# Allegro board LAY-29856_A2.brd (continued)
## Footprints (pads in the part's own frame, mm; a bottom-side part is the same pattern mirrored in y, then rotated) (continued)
WLCSP12_0P4_1P38X1P68MM_SMDP
  round 0.254 smd: A1(-0.4,0.6) A2(0,0.6) A3(0.4,0.6) B1(-0.4,0.2) B2(0,0.2) B3(0.4,0.2) C1(-0.4,-0.2) C2(0,-0.2) C3(0.4,-0.2) D1(-0.4,-0.6) D2(0,-0.6) D3(0.4,-0.6)
XQFN8_1P45X1P25MM
  rect 0.787x0.203 smd: 1(-0.75,0)
  rect 0.203x0.711 smd: 2(-0.4,-0.65) 3(0,-0.65) 4(0.4,-0.65) 6(0.4,0.65) 7(0,0.65) 8(-0.4,0.65)
  rect 0.711x0.203 smd: 5(0.75,0)
XTAL2-3P2X1P5-SM
  rect 1.092x1.905 smd: 1(-1.25,0) 2(1.25,0)
XTAL3_3P35X1P45_SM
  rect 0.406x2.108 smd: 1(1.2,0) 2(0,0) 3(-1.2,0)
XTL4_2P1X1P7MM_SM
  rect 0.762x0.711 smd: 1(-0.675,-0.5) 2(0.675,-0.5) 3(0.675,0.5) 4(-0.675,0.5)

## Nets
5V_SDA_PSW: C166.1 R210.1 U25.C2(VBUS1) U25.D1(VBUS2) U25.D2(VBUS3)
5V_SYS: C40.1 C41.1 C62.1 C63.1 C179.1 C180.1 D14.A J20.8 L20.2 R7.1 R38.1 R62.1 R71.1 R82.1 U3.1(IN) U3.3(S\H\D\N\) U6.1(IN)
5V_USB_OTG: C78.1 C81.1 C84.1 L3.2 R312.1 U1.59(USB_OTG1_VBUS) U7.C2(VBUS1) U7.D1(VBUS2) U7.D2(VBUS3)
5V_USB_OTG_S: J1.3(A2) R312.2
GND: C1.2 C2.2 C3.2 C4.2 C6.2 C7.2 C8.2 C9.2 C10.2 C11.2 C12.2 C13.2 C14.2 C15.2 C16.2 C17.2 C18.2 C19.2 C20.2 C21.2 C22.2 C23.2 C24.2 C25.2 C26.2 C28.2 C29.2 C30.2 C31.2 C32.2 C33.2 C35.2 C36.2 C37.2 C38.2 C39.2 C40.2 C41.2 C42.2 C43.2 C44.2 C45.2 C46.2 C47.2 C48.2 C49.2 C50.2 C51.2 C52.2 C53.2 C54.2 C55.2 C56.2 C57.2 C58.2 C59.2 C60.2 C62.2 C63.2 C64.2 C65.2 C66.2 C67.2 C68.2 C69.2 C70.2 C71.2 C72.2 C73.2 C74.2 C75.2 C76.2 C77.2 C78.2 C79.2 C80.2 C81.2 C82.2 C83.2 C84.2 C85.2 C86.2 C87.2 C88.1 C89.2 C90.2 C91.2 C92.2 C93.2 C94.2 C95.2 C96.2 C97.2 C98.2 C99.2 C100.2 C101.1 C104.2 C105.2 C106.2 C107.1 C108.2 C109.2 C110.1 C116.2 C117.2 C118.2 C119.2 C120.1 C121.1 C124.2 C125.2 C126.2 C127.2 C128.2 C129.2 C130.2 C131.2 C132.2 C133.2 C134.2 C135.2 C136.2 C137.2 C138.2 C139.2 C140.2 C141.2 C142.2 C143.2 C144.2 C145.2 C146.2 C147.2 C148.2 C149.2 C150.2 C151.2 C152.2 C153.2 C154.2 C155.2 C156.2 C157.2 C158.2 C159.2 C160.2 C161.2 C162.2 C163.2 C164.2 C165.2 C166.2 C167.2 C168.2 C169.2 C170.2 C171.2 C172.2 C173.2 C174.2 C175.2 C176.2 C177.2 C178.2 C179.2 C180.2 D1.A(ANODE) D3.4(CATHODE2) D11.3(ANODES) H1.1(NC_1) H2.1(NC_1) H3.1(NC_1) H4.1(NC_1) J1.7(A4) J1.8(B4) J1.9(A5) J1.10(B5) J2.2 J2.3 J7.1 J9.5(P5) J10.2 J11.1 J14.10(CHS_GND) J15.6(VSS) J15.SH1(GND1) J15.SH2(GND2) J15.SH3(GND3) J15.SH4(GND4) J16.4 J16.6 J16.8 J16.10 J16.12 J16.14 J16.16 J16.18 J16.20 J19.7 J20.6 J20.7 J23.5(P5) J29.3(A2) J29.5(A3) L5.2 L10.1 L12.2 Q1.3(G) Q4.2(SOURCE) Q9.1(SOURCE) R11.2 R31.2 R34.2 R42.2 R53.2 R54.2 R55.2 R57.2 R67.2 R70.2 R75.2 R86.1 R91.2 R103.1 R117.2 R120.2 R121.2 R122.2 R125.2 R126.2 R127.2 R131.2 R133.2 R134.2 R135.2 R137.2 R140.2 R141.2 R150.2 R151.2 R152.2 R178.2 R193.2 R196.2 R201.2 R203.2 R205.2 R211.2 R213.2 R244.2 R246.2 R248.2 R253.1 R254.1 R255.1 R256.1 R257.1 R258.1 R259.1 R260.1 R261.1 R262.1 R263.1 R264.1 SW1.3(NO1) SW1.6(NO2) SW2.1(A1) SW2.2(A2) SW3.1(A1) SW3.2(A2) SW4.1(A1) SW4.2(A2) SW5.1(A1) SW5.2(A2) TP2.1 TP3.1 TP4.1 TP5.1 TVS1.1(A1) TVS2.1(A1) TVS3.1(A1) TVS4.1(A1) TVS5.1(A1) U1.6(VSS1) U1.35(DCDC_GND) U1.40(VSS2) U1.51(TEST_MODE) U1.60(VSS3) U1.64(NGND_KEL0) U1.70(VSS4) U1.85(VSS5) U1.103(VSS6) U1.113(VSS7) U1.135(VSS8) U2.1(GND) U3.2(GND) U4.4(PGND) U4.6(AGND) U5.1(GND) U6.2(GND) U7.B3(GND1) U7.C3(GND2) U7.D3(GND3) U8.7(GND) U9.2(GND) U10.9(DGND) U10.20(SPKGND2) U10.24(SPKGND1) U10.28(AGND) U10.33(GND_PADDLE) U11.1(GND) U11.33(PADDLE) U12.2(A2) U13.4(GND) U14.6(VSSQ1) U14.12(VSSQ2) U14.28(VSS1) U14.41(VSS2) U14.46(VSSQ3) U14.52(VSSQ4) U14.54(VSS3) U15.4(GND) U16.2(VSS1) U16.8(VSSA) U16.33(EPAD) U17.2(GND) U18.2(A2) U19.2(A2) U20.2(A2) U21.2(GND) U22.4(GND) U22.5(DIR) U23.2(GND) U24.2(GND) U25.B3(GND1) U25.C3(GND2) U25.D3(GND3) U26.3(RSVD1) U26.5(GND1) U26.12(GND2) U26.13(RSVD2) U27.B2(GND) Y3.2 Y4.2 Y4.4
P3V3_SDA: C153.1 C154.1 C155.1 C156.1 C157.1 C163.1 J29.1(A1) R180.1 R181.1 R182.1 R183.2 R185.1 R194.1 R198.1 R202.1 R206.1 R207.1 R209.1 U15.1(VCCA) U16.1(VDD1) U16.7(VDDA) U16.11(VBAT) U17.5(VCC) U21.1(VCCA) U22.1(VCCA) U23.1(VCCA) U24.1(VCCA)
P5V0_SDA_USB_CONN_VBUS: J23.1(P1) L11.1 U18.1(A1)
P5V_SDA: C159.1 C164.1 C165.1 L11.2 R195.1 R200.1 R208.1 R212.1 U16.6(VREGIN) U25.B1(VINT1) U25.B2(VINT2) U25.C1(VINT3)
P5V_SDA_S: J1.5(A3) R208.2 R210.2
VDD_COIN_3V: D6.A J7.2 R17.1
VDD_HIGH_IN_3V3: C56.1 J5.1 R14.1 R45.2 R49.2
VDD_HIGH_IN_MCU: C19.1 C20.1 J5.2 R14.2 U1.69(VDD_HIGH_IN)
VDD_SNVS_3V3: C48.1 C60.1 D4.A R25.1 R36.2 R37.2 U5.4(VCC)
VDD_SNVS_IN: C23.1 J6.2 R16.2 R26.1 U1.55(VDD_SNVS_IN)
VDD_SOC_IN: C8.1 C9.1 C10.1 C11.1 C12.1 C13.1 C14.1 C15.1 C16.1 C17.1 C18.1 J4.1 R13.1 U1.5(VDD_SOC_IN1) U1.31(VDD_SOC_IN2) U1.39(VDD_SOC_IN3) U1.86(VDD_SOC_IN4) U1.102(VDD_SOC_IN5) U1.114(VDD_SOC_IN6) U1.134(VDD_SOC_IN7)
VDD_USB_3V: C79.1 C80.1 U1.61(VDD_USB_CAP)
VDDA_ADC_3P3_MCU: C6.1 C7.1 J3.2 R12.2 U1.73(VDDA_ADC_3P3)
VDDA_ADC_3V3: C47.1 J3.1 R12.1 R35.2
AUD_INT: R83.1 R84.1 U1.88(GPIO_AD_B1_04)
CAN1_H: C88.2 D11.2(CATHODE2) FL1.1 J10.1 R76.2 R77.1
CAN1_L: C90.1 D11.1(CATHODE1) FL1.2 J10.3 R78.2 R79.2
CAN1_RX: U1.32(GPIO_SD_B1_01) U9.4(RXD)
CAN1_TX: U1.33(GPIO_SD_B1_00) U9.1(TXD)
CAN_STBY: R74.1 R161.2 U1.76(GPIO_AD_B1_13)
CAN_VIO_3V3: C87.1 R72.1 R73.1 U9.5(VIO)
DC_5V_IN: C4.1 J2.1 Q1.1(D1) Q1.2(D2) Q1.5(D5) Q1.6(D6) Q1.7(D7) R1.1 R2.1 R6.1 TP1.1(PIN1)
DCDC_3V3: C134.1 C152.1 C171.1 D12.A J8.1 J14.1(LED_Y1) J14.12(LED_G12) J16.2 J19.8 J20.2 J20.4 L9.1 L13.1 R15.1 R19.1 R28.1 R35.1 R37.1 R45.1 R47.1 R56.1 R64.1 R66.1 R72.2 R80.1 R108.1 R109.1 R110.1 R111.1 R113.1 R114.1 R115.1 R118.2 R119.2 R123.2 R124.2 R128.2 R129.2 R130.2 R132.2 R136.2 R142.1 R144.1 R146.1 R147.1 R148.1 R149.1 R179.1 R186.1 R192.1 R197.1 R239.1 R359.1 U11.17(VDDIO) U15.8(VCCB) U21.6(VCCB) U22.8(VCCB) U23.6(VCCB) U24.6(VCCB) U27.A1(VIN)
DCDC_3V3_PG: C57.1 C58.1 TP9.1(TP) U4.1(PG) U6.3(S\H\D\N\)
DCDC_OUT: C38.1 C39.1 J4.2 L1.1 R13.2
ENET_B-CAST-OFF: R136.1 TP14.1(TP) U11.19(REF_CLK/B-CAST_OFF)
ENET_CONFIG0: R125.1 R128.1 U11.28(CONFIG0)
ENET_CONFIG1: R126.1 R129.1 U11.29(CONFIG1)
ENET_CRS_DV: R127.1 R130.1 R169.2 U1.97(GPIO_AD_B0_11) U11.18(CRS_DV/CONFIG2)
ENET_INT: R115.2 R137.1 R166.2 U1.84(GPIO_AD_B1_06) U11.21(INTRP/N\A\N\D\_\T\R\E\E\)
ENET_LED0/NWAYEN: J14.2(LED_Y2) R133.1 U11.30(LED0/NWAYEN)
ENET_LED1/SPEED: J14.11(LED_G11) R134.1 U11.31(LED1/SPEED)
ENET_MDC: R114.2 U1.115(GPIO_EMC_41) U11.12(MDC)
ENET_MDIO: R113.2 U1.116(GPIO_EMC_40) U11.11(MDIO)
ENET_PHYAD0: R119.1 R122.1 U11.13(PHYAD0)
ENET_PHYAD1: R120.1 R123.1 U11.14(PHYAD1)
ENET_RST: J16.13 R116.1 U1.107(GPIO_AD_B0_04)
ENET_RXD0: R135.1 R172.2 U1.98(GPIO_AD_B0_10) U11.16(RXD0/DUPLEX)
ENET_RXD1: R121.1 R124.1 R155.2 U1.99(GPIO_AD_B0_09) U11.15(RXD1/PHYAD2)
ENET_RXER: R131.1 R132.1 R170.2 U1.96(GPIO_AD_B0_12) U11.20(RXER/ISO)
ENET_RXM: C133.1 J14.8(RD-) R111.2 U11.4(RXM) U12.3(A3)
ENET_RXP: C132.1 J14.7(RD+) R110.2 U11.5(RXP) U12.1(A1)
ENET_TX_CLK: TP16.1(TP) U1.100(GPIO_AD_B0_08) U11.9(XI)
ENET_TXD0: R164.2 TP15.1(TP) U1.94(GPIO_AD_B0_14) U11.24(TXD0)
ENET_TXD1: R168.2 U1.93(GPIO_AD_B0_15) U11.25(TXD1)
ENET_TXEN: R171.2 U1.95(GPIO_AD_B0_13) U11.23(TXEN)
ENET_TXM: C131.1 J14.4(TD-) R109.2 U11.6(TXM) U12.4(A4)
ENET_TXP: C130.1 J14.3(TD+) R108.2 U11.7(TXP) U12.6(A6)
FLASH_3V3: C142.1 C143.1 R142.2 R143.1 R313.1 U13.8(VCC)
FLEXSPI_CLK: U1.24(GPIO_SD_B1_07) U13.6(SCK)
FLEXSPI_D0_A: U1.23(GPIO_SD_B1_08) U13.5(SI/IO0)
FLEXSPI_D1_A: U1.21(GPIO_SD_B1_10) U13.2(SO/IO1)
FLEXSPI_D2_A: U1.22(GPIO_SD_B1_09) U13.3(W\P\/IO2)
FLEXSPI_D3_A: R313.2 U1.25(GPIO_SD_B1_06) U13.7(H\O\L\D\/IO3)
FLEXSPI_SS0: R143.2 U1.19(GPIO_SD_B1_11) U13.1(C\E\)
GPIO_AD_B0_05: D5.C(CATHODE) J16.3 R148.2 R160.2 U1.106(GPIO_AD_B0_05)
GPIO_AD_B0_06: J26.2 R162.2 R197.2 U1.105(GPIO_AD_B0_06)
GPIO_AD_B0_07: J25.2 R156.2 R192.2 U1.101(GPIO_AD_B0_07)
GPIO_AD_B1_07: Q8.2(GATE) R55.1 R167.2 U1.83(GPIO_AD_B1_07)
GPIO_AD_B1_08: R154.2 U1.82(GPIO_AD_B1_08)
GPIO_AD_B1_09: R153.2 U1.81(GPIO_AD_B1_09)
GPIO_AD_B1_10: R69.1 R157.2 U1.80(GPIO_AD_B1_10)
GPIO_AD_B1_11: Q9.2(GATE) R68.2 R158.2 U1.79(GPIO_AD_B1_11)
GPIO_AD_B1_12: R65.1 R159.2 U1.78(GPIO_AD_B1_12)
GPIO_AD_B1_14: R92.2 R165.2 U1.75(GPIO_AD_B1_14) U10.17(SCLK)
GPIO_AD_B1_15: R93.2 R163.2 U1.74(GPIO_AD_B1_15) U10.18(SDIN)
GPIO_EMC_16: R254.2 R299.2 SW8.4(A4) U14.23(A0)
GPIO_EMC_17: R253.2 R300.2 SW8.3(A3) U14.24(A1)
GPIO_EMC_18: R264.2 R301.2 SW8.1(A1) U14.25(A2)
GPIO_EMC_19: R263.2 R302.2 U14.26(A3)
GPIO_EMC_20: R262.2 R303.2 U14.29(A4)
GPIO_EMC_21: R261.2 R288.2 U14.30(A5)
GPIO_EMC_22: R260.2 R271.2 R289.2 U14.31(A6)
GPIO_EMC_23: R259.2 R290.2 SW8.2(A2) U14.32(A7)
GPIO_EMC_24: R258.2 R295.2 R315.2 U14.33(A8)
GPIO_EMC_25: R257.2 R294.2 R314.2 U14.34(A9)
GPIO_EMC_26: R256.2 R270.2 R296.2 U14.35(A11)
GPIO_EMC_27: R255.2 R269.2 R298.2 U14.36(A12)
GPIO_SD_B1_02: R174.2 R249.2 R251.2 TP11.1(TP) U1.30(GPIO_SD_B1_02)
GPIO_SD_B1_03: R173.2 R250.2 R252.2 TP12.1(TP) U1.28(GPIO_SD_B1_03)
HP_JD: J11.5 R81.2 R84.2 TVS3.2(A2) U10.7(RINPUT3/JD3)
HP_L: C102.1 U10.31(HP_L)
HP_MIC1N: C110.2 C112.1 U10.4(LINPUT1)
HP_MIC1P: C115.1 C116.1 U10.2(LINPUT3/JD2)
HP_R: C103.1 U10.29(HP_R)
INT1_COMBO: R241.2 R242.2 R316.1 U1.27(GPIO_SD_B1_04)
INT2_COMBO: R240.2 R243.2 U1.26(GPIO_SD_B1_05)
JTAG_DACK: J16.19 R152.1
JTAG_DE: J16.17 R144.2
JTAG_MOD: R57.1 U1.109(GPIO_AD_B0_02)
JTAG_NSRST: D13.C J16.15 R145.2
JTAG_RTCK: J16.11 R151.1
JTAG_TCK: J16.9 J28.2 R150.1 U1.110(GPIO_AD_B0_01)
JTAG_TDI: C61.1 J16.5 R147.2 U1.108(GPIO_AD_B0_03)
JTAG_TMS: J16.7 J27.2 R146.2 U1.111(GPIO_AD_B0_00)
JTAG_VREF: J16.1 R149.2
MAIN_MIC2N: C114.2 C119.1 U10.5(RINPUT1)
MAIN_MIC2P: C107.2 C111.2 U10.6(RINPUT2)
MCU_DCDC_IN: C31.1 C32.1 C33.1 C35.1 J37.1 R33.1 R357.1 U1.34(DCDC_IN) U1.38(DCDC_IN_Q)
MCU_DCDC_IN_3V3: C55.1 J37.2 R44.2 R47.2 R357.2
MICBIAS: C98.1 R94.1 R95.1 U10.1(MICBIAS)
NVCC_GPIO_3V3: C66.1 C67.1 C68.1 C69.1 C70.1 C71.1 C72.1 C73.1 C74.1 C176.1 C177.1 C178.1 R56.2 U1.11(NVCC_GPIO1) U1.20(NVCC_GPIO2) U1.29(NVCC_GPIO3) U1.77(NVCC_GPIO4) U1.104(NVCC_GPIO5) U1.112(NVCC_GPIO6) U1.144(NVCC_GPIO7)
NVCC_SD: C64.1 C65.1 R51.1 R52.1 R58.1 R59.1 R60.1 TP10.1(TP) U6.5(OUT)
ONOFF: C172.1 SW2.3(B1) SW2.4(B2) U1.49(ONOFF)
OTG1_DN: L4.1 R61.2 U1.62(USB_OTG1_DN)
OTG1_DP: L4.4 R63.2 U1.63(USB_OTG1_DP)
PMIC_ON_REQ: R41.2 R43.2 U1.53(PMIC_ON_REQ)
POR_B: C28.1 D8.C D13.A D15.C(CATHODE) J21.1 J22.3 R22.2 R26.2 R179.2 R191.2 U1.50(P\O\R\) U15.7(B1)
POR_BUTTON: C173.1 R43.1 R50.1 SW3.3(B1) SW3.4(B2)
POWER_EN: R214.1 U16.31(ADC0_SE7B/PTD6/SPI0_PCS3/UART0_)
SAI1_MCLK: R90.1 U1.92(GPIO_AD_B1_00)
SAI1_RXD: R88.1 U1.87(GPIO_AD_B1_05)
SAI1_TX_BCLK: R87.1 U1.91(GPIO_AD_B1_01)
SAI1_TX_SYNC: R85.1 U1.90(GPIO_AD_B1_02)
SAI1_TXD: R89.1 U1.89(GPIO_AD_B1_03)
SD1_CLK: C140.1 R138.1 U1.45(GPIO_SD_B0_03)
SD1_CMD: R59.2 R362.1 U1.46(GPIO_SD_B0_02)
SD1_D0: R58.2 R363.1 U1.43(GPIO_SD_B0_04)
SD1_D1: R364.1 U1.42(GPIO_SD_B0_05)
SD1_D2: R360.1 U1.48(GPIO_SD_B0_00)
SD1_D3: R361.1 U1.47(GPIO_SD_B0_01)
SD_CD_SW: J15.9(DETECT) R139.2 R141.1 U1.41(GPIO_SD_B0_06)
SD_PWREN: D7.C R316.2
SDA_EXTAL: C161.1 U16.17(EXTAL0/PTA18/FTM0_FLT2/FTM_CLKI) Y3.3
SDA_JTAG_TCLK: J29.4(B2) U16.12(JTAG_TCLK/SWD_CLK/EZP_CLK/TSI0_)
SDA_JTAG_TDI: J29.8(B4) U16.13(JTAG_TDI/EZP_DI/TSI0_CH2/PTA1/U)
SDA_JTAG_TDO: J29.6(B3) U16.14(JTAG_TDO/TRACE_SWO/EZP_DO/TSI0_)
SDA_JTAG_TMS: J29.2(B1) R207.2 U16.15(JTAG_TMS/SWD_DIO/TSI0_CH4/PTA3/)
SDA_LED: D16.C(CATHODE) U16.29(PTD4/SPI0_PCS1/U\A\R\T\0\_\R\T\)
SDA_LED_R: D16.A(ANODE) R198.2
SDA_RST: J29.10(B5) R195.2 R196.1 TP24.1(PIN1) U16.19(R\E\S\E\T\)
SDA_RST_LED: D15.A(ANODE) R186.2
SDA_RST_TGTMCU_B: J24.1 U16.21(ADC0_SE9/TSI0_CH6/PTB1/I2C0_SDA)
SDA_RST_TGTMCU_J_B: J24.2 R188.1 R191.1
SDA_RX_EN: R193.1 R194.2 U21.5(DIR)
SDA_SPI0_CS: TP23.1(PIN1) U16.23(ADC0_SE4B/CMP1_IN0/TSI0_CH15/PT)
SDA_SPI0_RST_B: TP22.1(PIN1) U16.22(ADC0_SE15/TSI0_CH14/PTC1/SPI0_P)
SDA_SPI0_SCK: U16.26(PTC5/SPI0_SCK/LPTMR0_ALT2/I2S0_) U24.3(A)
SDA_SPI0_SIN: U16.28(CMP0_IN1/PTC7/SPI0_SIN/USB_SOF_) U22.3(2A)
SDA_SPI0_SOUT: U16.27(CMP0_IN0/PTC6/SPI0_SOUT/PDB0_EX) U23.3(A)
SDA_SWD_EN: R204.1 U17.6(Y\1\)
SDA_SWD_EN_B: R184.2 U16.16(N\M\I\/E\Z\P\_\C\S\/TSI0_CH5/PT)
SDA_SWD_EN_B_R: R182.2 R184.1 U17.1(A1)
SDA_SWD_EN_R: R204.2 R205.1 R206.2 U24.5(DIR)
SDA_SWD_OE: R199.1 U17.4(Y\2\)
SDA_SWD_OE_B: R187.2 U16.20(ADC0_SE8/TSI0_CH0/PTB0/I2C0_SCL)
SDA_SWD_OE_B_R: R185.2 R187.1 U17.3(A2)
SDA_SWD_OE_R: R199.2 R201.1 R202.2 U23.5(DIR)
SDA_USB_CONN_DN: J23.2(P2) R189.1 U20.1(A1)
SDA_USB_CONN_DP: J23.3(P3) R190.1 U19.1(A1)
SDA_USB_DN: R189.2 U16.4(USB0_DM)
SDA_USB_DP: R190.2 U16.3(USB0_DP)
SDA_USB_P5V_SENSE: R200.2 R203.1 U16.30(ADC0_SE6B/PTD5/SPI0_PCS2/U\A\R\)
SDA_USBSHIELD: J23.S1(SHLD1) J23.S2(SHLD2) J23.S3(SHLD3) J23.S4(SHLD4) L12.1
SDA_VOUT33: C162.1 R181.2 U16.5(VOUT33)
SDA_XTAL: C160.1 U16.18(XTAL0/PTA19/FTM1_FLT0/FTM_CLKIN) Y3.1
SDRAM_3V3: C144.1 C145.1 C146.1 C147.1 C148.1 C149.1 C150.1 C151.1 L13.2 R176.1 R265.1 R266.1 R267.1 R268.1 R269.1 R270.1 R271.1 R314.1 R315.1 U14.1(VDD1) U14.3(VDDQ1) U14.9(VDDQ2) U14.14(VDD2) U14.27(VDD3) U14.43(VDDQ3) U14.49(VDDQ4)
SEMC_A0: R299.1 U1.142(GPIO_EMC_16)
SEMC_A1: R300.1 U1.141(GPIO_EMC_17)
SEMC_A2: R301.1 U1.140(GPIO_EMC_18)
SEMC_A3: R302.1 U1.139(GPIO_EMC_19)
SEMC_A4: R303.1 U1.138(GPIO_EMC_20)
SEMC_A5: R288.1 U1.137(GPIO_EMC_21)
SEMC_A6: R289.1 U1.136(GPIO_EMC_22)
SEMC_A7: R290.1 U1.133(GPIO_EMC_23)
SEMC_A8: R295.1 U1.132(GPIO_EMC_24)
SEMC_A9: R294.1 U1.131(GPIO_EMC_25)
SEMC_A10: R297.1 U1.143(GPIO_EMC_15)
SEMC_A11: R296.1 U1.130(GPIO_EMC_26)
SEMC_A12: R298.1 U1.129(GPIO_EMC_27)
SEMC_BA0: R291.1 U1.2(GPIO_EMC_13)
SEMC_BA1: R293.1 U1.1(GPIO_EMC_14)
SEMC_CAS: R307.1 U1.7(GPIO_EMC_10)
SEMC_CKE: R306.1 U1.127(GPIO_EMC_29)
SEMC_CLK: R177.1 U1.126(GPIO_EMC_30)
SEMC_CS0: R311.1 U1.3(GPIO_EMC_12)
SEMC_D0: R272.2 U1.18(GPIO_EMC_00)
SEMC_D1: R273.2 U1.17(GPIO_EMC_01)
SEMC_D2: R274.2 U1.16(GPIO_EMC_02)
SEMC_D3: R275.2 U1.15(GPIO_EMC_03)
SEMC_D4: R276.2 U1.14(GPIO_EMC_04)
SEMC_D5: R277.2 U1.13(GPIO_EMC_05)
SEMC_D6: R278.2 U1.12(GPIO_EMC_06)
SEMC_D7: R279.2 U1.10(GPIO_EMC_07)
SEMC_D8: R283.2 U1.124(GPIO_EMC_32)
SEMC_D9: R284.2 U1.123(GPIO_EMC_33)
SEMC_D10: R285.2 U1.122(GPIO_EMC_34)
SEMC_D11: R286.2 U1.121(GPIO_EMC_35)
SEMC_D12: R287.2 U1.120(GPIO_EMC_36)
SEMC_D13: R280.2 U1.119(GPIO_EMC_37)
SEMC_D14: R281.2 U1.118(GPIO_EMC_38)
SEMC_D15: R282.2 U1.117(GPIO_EMC_39)
SEMC_DM0: R310.1 U1.9(GPIO_EMC_08)
SEMC_DM1: R309.1 U1.125(GPIO_EMC_31)
SEMC_DQS: C75.1 U1.128(GPIO_EMC_28)
SEMC_RAS: R308.1 U1.4(GPIO_EMC_11)
SEMC_WE: R304.1 U1.8(GPIO_EMC_09)
SENSOR_3V3: C167.1 C168.1 R239.2 R240.1 R241.1 R245.1 R247.1 R249.1 R250.1 U26.1(VDDIO) U26.14(VDD)
SPK_LN: R105.1 U10.23(SPK_LN)
SPK_LP: R107.1 U10.25(SPK_LP)
SPK_RN: R104.1 U10.19(SPK_RN)
SPK_RP: R106.1 U10.22(SPK_RP)
SW1_RST_B: C158.1 J22.2 SW5.3(B1) SW5.4(B2)
SWD_CLK_TGTMCU_BUF: J28.1 U24.4(B)
SWD_DIO_TGTMCU_BUF: J27.1 U22.6(2B) U23.4(B)
TC_EXTAL_TP: TP20.1(PIN1) U16.10(EXTAL32)
TC_SDA_USB_ID_TP: J23.4(P4) TP19.1(PIN1)
TC_XTAL_TP: TP21.1(PIN1) U16.9(XTAL32)
TP_2102_A: TP17.1(PIN1) U15.3(A2)
TP_2102_B: TP18.1(PIN1) U15.6(B2)
UART1_RX_TGTMCU_BUF: J25.1 U21.4(B)
UART1_RX_TGTMCU_R: U16.25(PTC4/SPI0_PCS0/UART1_TX/FTM0_CH) U21.3(A)
UART1_TX_TGTMCU_BUF: J26.1 U22.7(1B)
UART1_TX_TGTMCU_R: U16.24(CMP1_IN1/PTC3/SPI0_PCS1/UART1_R) U22.2(1A)
USER_BUTTON: C174.1 SW4.3(B1) SW4.4(B2) TP6.1(TP) U1.52(WAKEUP)
VAUD_3V3: C91.1 C92.1 C93.1 C94.1 R80.2 R81.1 R92.1 R93.1 U10.8(DCVDD) U10.10(DBVDD) U10.32(AVDD)
VLDO_3V3: C42.1 C43.1 R32.1 R36.1 R44.1 R49.1 U3.5(OUT)
VSD_3V3: C30.1 C138.1 C139.1 J15.4(VDD) R358.1 U27.A2(VOUT)
VTRG_FAULT_B: R209.2 U16.32(PTD7/CMT_IRO/UART0_TX/FTM0_CH7/) U25.A2(F\A\U\L\T\)
WALL_OV_BASE: Q3.1(B) R5.2
WALL_OV_CTL: D1.C(CATHODE) R3.2 R5.1
WALL_OVP_LED: D2.A Q3.3(C) R10.1
N99781517: D4.C D6.C J6.1 R16.1 R17.2
N99781633: C21.1 C22.1 U1.65(VDD_HIGH_CAP)
N99781636: C24.1 U1.56(VDD_SNVS_CAP)
N99781637: C25.1 C26.1 U1.72(NVCC_PLL)
N99781671: L1.2 U1.36(DCDC_LP)
N99781682: C44.1 U1.57(RTC_XTALI) Y2.1
N99781687: C45.1 U1.58(RTC_XTALO) Y2.2
N99781695: C37.1 R30.2 U1.68(XTALO) Y4.1
N99781702: C36.1 R30.1 R31.1 U1.67(XTALI) Y4.3
N99781716: C29.1 R20.2 R21.1 U2.3(VCC)
N99781728: R21.2 R22.1 U2.2(R\E\S\E\T\)
N99781740: C61.2 D10.C R53.1
N99781746: D9.A D10.A R46.1 U5.3(M\R\)
N99781747: C52.1 C53.1 J8.2 L2.2 R40.1 TP8.1(TP) U4.5(OUT)
N99781749: C54.1 R39.2 R41.1 R46.2 U4.8(EN) U5.2(R\E\S\E\T\)
N99781753: C59.1 D9.C R50.2
N99781762: C49.1 C50.1 C51.1 R38.2 R39.1 U4.2(VIN)
N99781782: R40.2 R42.1 U4.7(FB)
N99781791: L2.1 U4.3(SW)
N99808656: C76.1 C77.1 R60.2 U1.44(NVCC_SD0)
N99815013: C126.1 C127.1 L9.2 U11.3(VDDA_3.3)
N99815680: C128.1 C129.1 U11.2(VDD_1.2)
N99815919: C135.1 J14.6(CT1)
N99815924: C136.1 J14.5(CT2)
N99816488: J14.13(SH1) J14.14(SH2) L10.2
N99820323: R117.1 U11.10(REXT)
N99825452: C95.1 C96.1 C97.1 C99.1 R82.2 U10.21(SPKVDD2) U10.26(SPKVDD1)
N99827287: C100.1 U10.27(VMID)
N99827729: R83.2 U10.15(ADCLRC/GPIO1)
N99827749: R85.2 U10.13(DACLRC)
N99827769: R87.2 U10.12(BCLK)
N99827789: R88.2 U10.16(ADCDAT)
N99827809: R89.2 U10.14(DACDAT)
N99827829: R90.2 U10.11(MCLK)
N99827958: C120.2 C122.1 J12.2 R104.2
N99827962: C122.2 C124.1 J12.1 R106.2
N99828318: C121.2 C123.1 J13.2 R105.2
N99828322: C123.2 C125.1 J13.1 R107.2
N99833003: J9.S1(SHLD1) J9.S2(SHLD2) J9.S3(SHLD3) J9.S4(SHLD4) L5.1
N99833017: J9.1(P1) L3.1 U8.6(VBUS)
N99833020: J9.4(P4) R68.1 U8.3(USB ID)
N99833038: J9.2(P2) L4.2 R61.1 U8.1(DM)
N99833040: J9.3(P3) L4.3 R63.1 U8.2(DP)
N99838171: D12.C R145.1
N99881896: R183.1 U15.5(OE)
N99882483: J22.1 R180.2 R188.2 U15.2(A1)
N99903207: C102.2 L6.1 R86.2
N99903209: C103.2 L7.1 R91.1
N99903219: C104.1 J11.3 L7.2 TVS4.2(A2)
N99903223: C101.2 J11.2 L6.2 TVS2.2(A2)
N99903738: J11.4 L8.2 TVS5.2(A2)
N99904959: C112.2 R97.2 R100.1
N99904961: C115.2 C117.1 C118.1 L8.1 R100.2
N99904975: C108.1 C109.1 R94.2 R97.1
N99907436: C113.2 R102.2 R103.2
N99907447: C114.1 R99.2 R101.2 R102.1
N99907449: C111.1 R96.2 R98.2 R99.1
N99907458: C105.1 C106.1 C113.1 R95.2 R96.1
N99907542: P1.1(OUT) R98.1
N99907546: P1.2(GND) R101.1
N99909350: R247.2 R248.1 U26.7(SA0/MISO)
N99909356: R244.1 U26.16(RST)
N99909379: R252.1 U26.6(SDA/MOSI)
N99909383: R251.1 U26.4(SCL/SCLK)
N99909400: C170.1 U26.2(BYP)
N99909418: C169.1 U26.8(CRST)
N99909466: R243.1 U26.9(INT2)
N99909468: R242.1 U26.11(INT1)
N99909488: R245.2 R246.1 U26.10(SA1/C\S\)
N99916564: J18.5 R163.1
N99916634: J18.6 R165.1
N99916953: J20.3 J21.2
N99916957: D14.C J20.5
N99917118: J19.9 R173.1
N100002783: C46.1 R33.2 U1.37(DCDC_PSWITCH)
N100054133: Q4.1(GATE) R10.2 R11.1
N100054172: C1.1 C2.1 C3.1 J1.1(A1) JP1.2 Q2.1(D1) Q2.2(D2) Q2.5(D5) Q2.6(D6) Q2.7(D7) TVS1.2(A2)
N100054253: C5.2 D2.C Q2.3(G) R4.2 R8.1
N100054255: R8.2 R9.1
N100054257: R9.2 SW1.5(COMMON2)
N100054299: C5.1 JP1.1 Q1.4(S1) Q1.8(S2) Q2.4(S1) Q2.8(S2) Q3.2(E) R1.2 R2.2 R3.1 R4.1
N100054525: D3.3(ANODE2) R7.2
N100054552: D3.1(ANODE1) R6.2
N100054568: D3.2(CATHODE1) Q4.3(DRAIN)
N100054652: J1.2(B1) J1.4(B2) J1.6(B3) L20.1
N100226419: R266.2 SW8.6(B3)
N100226426: R267.2 SW8.7(B2)
N100226433: R268.2 SW8.8(B1)
N100585007: J15.7(DAT0) R363.2
N100585009: J15.8(DAT1) R364.2
N100585016: J15.1(DAT2) R360.2
N100585038: J15.3(CMD) R362.2
N100585089: J15.2(CD/DAT3) R140.1 R361.2
N100640762: J19.10 R174.1
N100756566: TP7.1(TP) U1.71(GPANAIO)
N100757315: TP13.1(TP) U1.66(U\S\B\_\O\T\G\1\_\C\H\D\)
N100763759: C141.1 J15.5(CLK) R138.2
N100784802: J18.1 R157.1
N100784828: J18.2 R158.1
N100784935: J18.3 R159.1
N100784954: J18.4 R161.1
N100872888: R19.2 R20.1 R25.2
N100979684: R32.2 R34.1 U3.4(FB)
N101050998: C137.1 R116.2 R118.1 U11.32(R\S\T\)
N101100421: R139.1 R358.2 R359.2
N101108824: D5.A(ANODE) R15.2
N101139052: C82.1 C83.1 R62.2 U7.B1(VINT1) U7.B2(VINT2) U7.C1(VINT3)
N101140611: Q9.3(DRAIN) R66.2 R69.2 R70.1 U7.A1(EN)
N101140956: R64.2 R65.2 U7.A2(F\A\U\L\T\)
N101141371: R67.1 U7.A3(ILIM)
N101160132: R211.1 U25.A3(ILIM)
N101160928: R212.2 R213.1 R214.2 U25.A1(EN)
N101219622: C175.1 R177.2 U14.38(CLK)
N101253829: C85.1 C86.1 R71.2 U9.3(VCC)
N101254531: C89.1 R77.2 R78.1
N101254622: FL1.4 R76.1 U9.7(CANH)
N101254624: FL1.3 R79.1 U9.6(CANL)
N101255204: R73.2 R74.2 R75.1 U9.8(S)
N101312524: Q8.3(DRAIN) R52.2
N101312526: Q8.1(SOURCE) R51.2 R54.1 U6.4(FB)
N101449115: D7.A D8.A R28.2 R29.1
N101449483: R29.2 U27.B1(EN)
N101471655: J19.1 R167.1
N101471657: J19.2 R168.1
N101471659: J19.6 R172.1
N101471661: J19.3 R169.1
N101471663: J19.5 R171.1
N101471665: J19.4 R170.1
N101505077: J17.5 R160.1
N101505079: J17.3 R155.1
N101505081: J17.6 R162.1
N101505083: J17.8 R166.1
N101505085: J17.7 R164.1
N101505087: J17.4 R156.1
N101505089: J17.2 R154.1
N101505091: J17.1 R153.1
N101507443: R272.1 U14.2(DQ0)
N101507450: R273.1 U14.4(DQ1)
N101507457: R274.1 U14.5(DQ2)
N101507470: R275.1 U14.7(DQ3)
N101507472: R276.1 U14.8(DQ4)
N101507474: R277.1 U14.10(DQ5)
N101507491: R278.1 U14.11(DQ6)
N101507493: R279.1 U14.13(DQ7)
N101507495: R283.1 U14.42(DQ8)
N101507512: R284.1 U14.44(DQ9)
N101507514: R285.1 U14.45(DQ10)
N101507516: R286.1 U14.47(DQ11)
N101507533: R287.1 U14.48(DQ12)
N101507535: R280.1 U14.50(DQ13)
N101507537: R281.1 U14.51(DQ14)
N101507548: R282.1 U14.53(DQ15)
N101509422: R297.2 U14.22(A10)
N101509590: R291.2 U14.20(BA0)
N101509597: R293.2 U14.21(BA1)
N101509855: R178.1 R306.2 U14.37(CKE)
N101509857: R309.2 U14.39(DQMH)
N101509859: R310.2 U14.15(DQML)
N101509861: R308.2 U14.18(R\A\S\)
N101509863: R304.2 U14.16(W\E\)
N101510168: R307.2 U14.17(C\A\S\)
N101511316: R176.2 R311.2 U14.19(C\S\)
N101583028: R265.2 SW8.5(B4)
N101594808: TP25.1(TP) U1.54(PMIC_STBY_REQ)

Pads without a net: J11 6; J14 9; J20 1; J29 7 9; SW1 1 2 4; U8 4 5; U10 3 30; U11 8 22 26 27; U12 5; U14 40; U26 15

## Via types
v1: diameter 0.457, hole 0.203, TOP to BOTTOM, 1647 vias

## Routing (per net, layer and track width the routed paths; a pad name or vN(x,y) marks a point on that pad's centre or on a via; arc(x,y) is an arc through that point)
5V_SDA_PSW: length 0.8
  TOP w0.254: U25.C2 U25.D2 U25.D1
5V_SYS: length 148.9
  TOP w0.305: v1(10.29,25.02) 8.89,23.62 R7.1
  TOP w0.381: R82.1 52.84,18.41 v1(48.64,18.41) ; 27.1,25.91 31.11,25.91 35.94,21.08 v1(35.94,18.92) ; R62.1 v1(12.19,54.1) ; v1(35.56,72.14) C180.1 v1(39.5,72.14) 42.42,75.06 42.42,87.24 44.08,88.9 65.02,88.9 73.91,80.01 98.96,80.01 D14.A 99.21,78.49 J20.8 ; v1(42.16,69.85) 42.54,69.48 R71.1
  BOTTOM w0.381: v1(12.19,54.1) v1(15.75,54.1) ; v1(39.5,72.14) 39.5,71.37 41.02,69.85 v1(42.16,69.85) ; v1(35.94,18.92) 44.96,18.92 45.47,18.41 v1(48.64,18.41) ; v1(10.29,25.02) v1(11.68,26.42) ; v1(35.56,72.14) 32.13,72.14 28.45,68.45 24.51,68.45 22.1,66.04 v1(20.19,66.04)
  vias: v1(13.46,41.27) v1(13.97,40.39) v1(14.48,41.27) v1(14.99,40.39) v1(15.49,41.27) v1(16.26,47.37) v1(16.76,46.48) v1(17.27,47.37) v1(17.78,46.48) v1(18.29,47.37)
5V_USB_OTG: length 42.3
  TOP w0.254: U7.D1 U7.D2 U7.C2
  TOP w0.305: v1(40.13,44.58) 42.55,44.58 43.23,45.26 44.75,45.26 C78.1 45.35,45.6 46.14,46.39 U1.59 ; v1(38.61,44.45) 37.47,44.45 36.83,45.09 33.27,45.09 33.15,44.96 28.19,44.96 27.94,45.21 22.1,45.21 21.84,44.96 13.84,44.96 13.31,45.49 12.55,45.49 11.91,46.13 9.75,46.13 8.52,47.36 R312.1
  BOTTOM w0.381: v1(38.61,44.45) 38.73,44.58 v1(40.13,44.58)
5V_USB_OTG_S: length 53.3
  TOP w0.381: R312.2 8.12,46.62 9.19,45.54 v1(10.41,45.54) ; v1(10.16,41.53) 10.16,26.16 13.84,22.48 13.84,18.16 16.89,15.11 v1(21.21,15.11)
  BOTTOM w0.381: v1(10.16,41.53) 10.16,42.29 10.92,43.05 10.92,45.03 v1(10.41,45.54) ; v1(21.21,15.11) 31.75,15.11 J1.3
GND: length 1669.4
  TOP w0.127: v1(64.8,68.3) 65.13,68.3 65.41,68.58 v1(65.41,69.34) ; v1(103.89,62.61) 103.63,62.61 102.36,63.88 v1(102.36,64.14) 102.11,64.14 100.71,65.53 v1(100.71,65.79) 100.46,65.79 98.81,67.44 v1(98.81,67.69) 98.55,67.69 96.65,69.6 v1(96.65,69.85) 96.39,69.85 95.12,71.12 92.84,71.12 v1(92.71,71.25) 92.58,71.12 89.72,71.12 v1(89.59,71.25) 89.46,71.12 85.92,71.12 v1(85.79,71.25) 85.66,71.12 82.68,71.12 v1(82.55,71.25) 82.42,71.12 79.76,71.12 v1(79.63,71.25) 79.5,71.12 75.95,71.12 v1(75.82,71.25) 75.69,71.37 74.04,71.37 73.66,70.99 v1(72.77,70.99) 72.39,70.99 v1(70.23,68.83) 68.91,67.51 65.02,67.51 58.22,60.71 v1(57.78,60.71) ; 82.42,47.37 84.45,47.37 v1(84.58,47.5) 84.71,47.37 88.27,47.37 88.37,47.27 v1(88.42,47.27) v1(89.41,47.27) ; v1(35.81,55.68) v1(38.23,55.68) 39.19,55.68 39.37,55.85 40.66,55.85 C76.2 ; 70.23,59.69 72.14,59.69 72.26,59.82 v1(72.26,60.2) v1(75.69,60.2) v1(77.72,60.2) v1(79.76,60.2) 80.64,60.2 80.9,60.45 v1(80.9,61.72) 80.9,62.74 81.03,62.87 v1(82.55,62.87) 82.91,63.22 87.17,63.22 v1(87.66,62.74) ; U13.4 64.01,72.39 v1(63.63,72.01) ; v1(63.75,61.21) 63.75,61.47 65.91,63.63 v1(66.29,63.63) v1(68.2,63.63) v1(69.98,63.63) 70.48,63.63 v1(71.37,64.52) v1(72.64,65.79) 73.62,66.76 v1(73.91,66.76) v1(76.07,66.76) v1(78.49,66.76) v1(80.77,66.76) v1(83.31,66.76) ; v1(83.31,66.76) v1(85.72,66.76) v1(88.01,66.76) v1(88.9,66.76) ; v1(83.31,66.76) 82.68,66.13 v1(82.68,65.91) 82.68,65.79 83.06,65.41 88.65,65.41 v1(88.84,65.21) v1(89.66,64.39) 90.04,64.01 90.55,64.01 91.8,62.76 92.41,62.76 v1(92.58,62.59) ; v1(72.26,55.24) v1(75.44,55.24) ; v1(104.25,47.87) 103.49,47.87 v1(103.25,47.62) v1(101.73,46.1) v1(99.69,44.07) v1(97.79,42.16) v1(95.89,40.26) 94.74,39.12 v1(94.23,39.12) v1(91.41,39.12) v1(88.39,39.12) v1(85.47,39.12) v1(82.42,39.12) v1(79.5,39.12) v1(76.83,39.12) 76.15,39.12 73.3,41.96 71.48,41.96 v1(71.25,42.19) v1(70.03,43.41) ; v1(75.01,50.34) 76.2,49.15 80.64,49.15 v1(81.22,48.58) ; v1(85.93,43.05) 86.31,43.43 v1(88.14,43.43) v1(90.81,43.43) v1(93.65,43.43) v1(95.17,44.96) 95.17,47.29 95.63,47.75 v1(95.76,47.75) ; U1.64 45.92,43.89 45.81,43.78 44.16,43.78 43.81,43.43 ; 74.68,49.28 72.64,49.28 72.52,49.4 C75.2 ; v1(54.46,60.86) 54.46,61.24 56.85,63.63 57.17,63.63 v1(57.8,64.25) 61.09,67.54 v1(61.09,67.69) ; v1(73.03,61.72) v1(74.42,63.12) 75.18,63.88 80.98,63.88 v1(81.1,64.01) ; v1(37.85,54.22) 37.43,54.64 35.13,54.64 v1(33.76,56.01) v1(32.94,56.82) 32.59,57.18 v1(32.59,58.93) 32.59,60.25 v1(32,60.83) v1(32,63.63) v1(32,66.8) v1(32,68.58) 32,70.92 v1(32.59,71.5) v1(32.59,72.9) 32.59,73.58 30.99,75.18 28.19,75.18 v1(27.56,75.82) v1(25.65,77.72) 25.27,78.11 25.27,79.76 v1(24.77,80.26) ; 76.07,33.15 v1(78.61,30.61) ; v1(41.66,42.55) v1(37.85,42.55) 36.32,42.55 35.56,43.31 v1(34.29,43.31) v1(27.56,43.31) v1(19.81,43.31) v1(13.51,43.31) 13,42.8 v1(9.65,42.8) ; v1(91.19,68.02) 91.06,67.89 91.06,67.06 94.23,63.88 94.49,63.88 95.63,62.74 v1(95.63,62.61) ; v1(70.76,45.34) v1(72.34,43.76) 72.57,43.54 74.19,43.54 v1(74.68,43.05) v1(76.58,41.15) 76.83,40.89 83.82,40.89 v1(83.95,41.02) 83.95,41.22 84.25,41.53 88.47,41.53 v1(88.65,41.71) v1(91.06,41.71) v1(93.73,41.71) 94.21,41.71 98.93,46.43 v1(98.93,47.83) ; v1(64.64,71.37) 64.9,71.37 65.41,70.87 v1(65.41,70.36) ; v1(66.04,31.58) v1(70.48,31.58) 71.32,31.58 v1(72.46,30.43) v1(75.08,27.81) 75.74,27.15 v1(75.74,26.16) v1(75.74,21.97) v1(75.74,18.54) 75.74,17.65 75.87,17.53 v1(77.47,17.53) ; v1(39.12,43.81) 36.96,43.81 v1(36.32,44.45) 27.69,44.45 v1(27.56,44.58) v1(23.24,44.58) 22.48,44.58 22.35,44.45 13.54,44.45 12.9,45.09 12.32,45.09 12.06,45.34 v1(11.81,45.34) ; v1(61.47,71.75) 62.31,71.75 v1(62.99,71.07) ; v1(75.95,62.99) 75.56,62.99 73.91,61.34 v1(73.91,61.09) ; v1(83.44,43.41) v1(80.77,43.41) v1(78.61,43.41) 76.81,43.41 v1(76.62,43.6) v1(75.26,44.96) 74.5,45.72 v1(72.77,45.72) ; v1(84.84,9.53) 84.45,9.14 78.2,9.14 v1(77.9,9.45) v1(76.5,10.84) v1(74.6,12.75) 73.53,13.81 v1(73.53,15.88) v1(73.53,21.21) v1(73.53,25.76) 73.53,26.26 70.59,29.21 v1(70.48,29.21) 69.47,29.21 v1(68.99,29.69) v1(65.79,29.69) ; 31.11,68.53 31.11,60.45 31.8,59.77 31.8,56.85 34.62,54.03 36.65,54.03 37.72,52.96 38.99,52.96 39.37,52.58 v1(40.26,52.58) ; v1(31.5,73.15) 31.5,73.33 v1(30.91,73.91) 30.53,74.3 26.8,74.3 v1(26.42,74.68) v1(24.89,76.2) 21.97,79.12 v1(21.97,79.76) ; v1(36.36,52.29) 35.84,52.81 33.81,52.81 v1(33.15,53.47) v1(31.11,55.5) 30.35,56.27 v1(30.35,57.53) 30.35,58.53 v1(28.55,60.33) 28.07,60.81 v1(28.07,61.72) v1(28.07,64.01) v1(28.07,66.04) v1(28.07,69.09) v1(28.07,71.75) v1(27.43,72.39) 25.78,72.39 v1(24.89,73.28) v1(23.24,74.93) v1(21.72,76.45) v1(19.81,78.36) 18.73,79.44 v1(18.73,80.26) 18.29,80.71 18.29,82.3 19.05,83.06 v1(24.77,83.06) 27.18,83.06 27.81,82.42 v1(27.81,81.53) 27.81,80.39 v1(29.46,78.74) v1(31.75,76.45) v1(33.53,74.68) 33.73,74.47 33.73,69.88 v1(33.88,69.72) v1(33.88,67.56) 33.91,67.54 33.91,66.57 34.75,65.73 v1(34.75,63.63) v1(34.75,61.34) v1(34.75,59.31) 34.75,58.09 35.76,57.07 43.31,57.07 44.49,55.89 C17.2 ; v1(72.26,54.23) 75.18,54.23 ; v1(61.37,61.42) 61.37,61.67 65.48,65.79 v1(65.79,65.79) v1(67.44,65.79) v1(69.34,65.79) 69.77,65.79 72.77,68.78 81.1,68.78 v1(81.28,68.96) 81.28,69.22 81.58,69.52 93.93,69.52 v1(94.11,69.34) 94.36,69.09 94.36,68.71 98.17,64.9 98.17,64.26 98.55,63.88 v1(98.55,63.12)
  TOP w0.152: v1(137.29,65.41) U21.2 ; v1(137.67,51.31) U24.2 ; v1(137.67,56.01) U23.2
  TOP w0.178: v1(90.55,46.1) 89.79,46.1 89.46,46.43 86.54,46.43 v1(86.49,46.48)
  TOP w0.203: U15.4 119.65,61.83 v1(119.89,61.59) ; v1(135.89,61.59) 136.28,61.59 136.48,61.39 U22.4 ; v1(135.13,61.59) 135.13,61.4 U22.5
  TOP w0.254: U7.B3 U7.C3 U7.D3 ; U27.B2 22.35,57.4 v1(21.97,57.4) ; U1.103 64.16,36.9 v1(64.39,36.68) ; v1(72.26,47.5) 72.77,46.99 75.82,46.99 v1(76.07,46.74) v1(77.47,45.34) 77.72,45.09 v1(80.52,45.09) v1(83.57,45.09) v1(86.11,45.09) 87.3,45.09 v1(87.4,45.19) 87.5,45.09 92.2,45.09 v1(92.58,45.47) 92.58,47.12 v1(92.2,47.5) ; U25.B3 U25.C3 U25.D3 ; v1(86.49,46.48) v1(83.31,46.48) v1(80.29,46.48) 78.56,46.48 v1(78.49,46.56) 77.9,46.56 v1(77.47,46.99) 76.45,48.01 v1(76.07,48.01) v1(73.28,48.01)
  TOP w0.279: v1(120.65,79.5) 120.65,79.25 121.18,78.71 U16.8 ; U17.2 v1(122.17,68.83)
  TOP w0.305: C58.2 C57.2 v1(20.95,30.09) ; U4.6 v1(23.06,34.04) ; v1(48.64,50.32) 48.57,50.39 U1.51 ; U5.1 v1(17.41,33.79) ; v1(124.33,77.47) 124.19,77.62 U16.2 ; U1.70 48.39,40.89 v1(48.51,40.77) ; v1(59.05,29.79) 58.57,29.79 58.27,29.49 U10.9 ; Q9.1 14.62,47.26 v1(14.48,47.12) ; U26.5 v1(56.77,81.93) ; U1.6 64.16,58.19 v1(64.01,58.04) ; U1.35 49.66,58.29 50.04,57.91 v1(50.55,57.91) ; v1(54.86,39.37) 55.16,39.07 U1.85 ; v1(26.04,28.19) 25.4,28.19 C50.2 25.4,27.43 v1(26.04,27.43) ; v1(20.19,26.67) C49.2 v1(19.18,27.81) ; v1(24.26,31.24) 23.71,30.69 U4.4 ; C21.2 v1(37.97,40.01) ; C59.2 v1(21.22,38.86) ; Q4.2 v1(13.58,15.76) ; v1(88.92,15.75) 88.92,16.11 88.62,16.41 U11.1 ; U26.3 v1(56.77,82.93) ; SW2.2 v1(2.71,81.5) ; SW3.2 v1(2.71,37.93) ; U10.20 56.26,27.05 v1(56.52,26.8) ; v1(44.32,45.97) 44.2,45.85 C45.2 ; U1.113 v1(67.16,41.89) ; U26.13 64.75,83.93 v1(65.02,84.2) ; U10.28 v1(56.26,23.5) ; D3.4 v1(13.04,21.3) ; v1(67.18,52.96) 67.25,52.89 U1.135 v1(69.98,52.89) ; U1.64 48.21,43.89 v1(48.51,44.2) ; SW2.1 v1(2.71,68.16) ; U1.60 48.44,45.89 v1(48.51,45.81) ; v1(7.62,45.21) 7.87,44.96 U8.7 ; C60.2 v1(19.68,38.86) ; v1(28.19,10.03) 27.3,10.03 v1(27.3,10.79) ; U10.24 53.75,25.05 v1(53.34,24.64) ; SW4.2 v1(2.71,67.14) ; v1(24.27,37.1) C52.2 v1(25.27,37.97) ; C19.2 v1(45.34,36.45) ; R42.2 v1(21.72,34.17) ; v1(64.14,39.37) 64.16,39.34 U1.103 ; R67.2 9.91,46.86 v1(9.65,47.12) ; U26.12 v1(65.53,83.43) ; C51.2 v1(25.65,26.54) ; C2.2 v1(25.28,9.77) ; R53.2 v1(24.12,38.86) ; SW3.1 v1(2.71,24.55) ; C22.2 v1(36.96,40.01) ; v1(45.72,55.89) U1.40 ; SW4.1 v1(1.3,56.03) ; C53.2 v1(25.15,30.23) ; D1.A v1(17.59,13.15) ; C54.2 v1(20.19,34.54) ; R11.2 v1(10.04,13.72)
  TOP w0.381: 8.76,38.99 v1(9.53,38.99) ; R34.2 22.23,46.35 v1(19.94,46.35) C41.2 ; v1(135.89,61.59) 135.89,62.1 136.01,62.22 R193.2 ; C156.2 120.66,79.51 v1(120.65,79.5) ; C136.2 v1(108.58,13.59) ; U3.2 v1(19.68,48.51) ; v1(105.03,17.14) 105.03,17.78 103.89,18.92 101.85,18.92 101.6,18.67 v1(100.33,18.67) 97.92,18.67 v1(97.54,19.05) 95.63,20.95 v1(97.54,20.95) v1(101.98,20.95) 103.76,20.95 v1(105.73,18.99) 107.19,17.53 v1(111.38,17.53) ; v1(62.61,29.97) C94.2 C92.2 v1(63.37,29.08) ; J14.10 v1(111.51,8.5) ; C109.2 64.26,26.16 v1(64.14,26.16) ; C165.2 v1(129.29,72.9) ; R248.2 v1(62.1,77.22) ; C88.1 v1(51.31,83.57) ; 128.52,37.08 J16.4 128.52,39.62 ; Y4.2 41.23,40.51 v1(42.04,40.51) 42.28,40.76 C36.2 ; R75.2 v1(53.33,72.64) ; C63.2 v1(18.41,67.82) ; C172.2 v1(9.91,66.93) ; C128.2 v1(87.38,10.03) ; C166.2 v1(134.49,69.85) ; C80.2 v1(39.5,47.5) ; v1(90.55,46.99) v1(90.55,46.1) C175.2 ; C29.2 26.54,58.8 v1(26.29,59.05) 25.65,59.05 C171.2 ; C134.2 v1(82.55,22.35) ; v1(7.37,51.82) C82.2 v1(6.35,52.96) ; J16.16 113.28,36.96 ; v1(44.7,41.53) 44.32,41.91 R31.2 ; R134.2 v1(83.44,10.17) ; C107.1 70.74,26.54 v1(71.12,26.16) 70.87,25.91 C106.2 ; C101.1 v1(60.83,18.16) ; v1(83.19,51.05) 83.45,50.79 U14.28 ; C129.2 v1(88.27,10.03) ; v1(20.19,53.59) 20.19,52.83 C40.2 19.43,53.09 v1(19.43,53.59) ; v1(11.3,52.07) C83.2 v1(12.19,52.96) R70.2 ; 123.44,39.62 J16.8 123.44,36.83 ; J15.SH1 v1(29.37,84.42) ; R135.2 v1(80.01,24.5) ; U14.41 v1(93.85,47.75) ; U20.2 v1(125.62,82.42) ; v1(125.62,82.42) 126,82.04 C157.2 ; v1(125.62,82.42) 125.48,82.28 v1(125.48,79.71) ; v1(134.37,52.45) 135.64,52.45 136.02,52.83 R201.2 ; 125.98,39.62 J16.6 125.98,37.08 ; R126.2 v1(80.39,10.03) ; C105.2 v1(71.88,25.91) ; v1(27.18,69.09) 26.66,69.09 R141.2 ; R86.1 59.69,19.94 v1(60.07,20.32) C93.2 ; C125.2 v1(50.03,19.95) ; C152.2 v1(115.32,65.41) ; C164.2 v1(128.78,74.17) ; H4.1 101.85,6.1 ; H4.1 104.14,11.56 ; H4.1 99.44,11.68 ; H4.1 104.14,6.99 ; H4.1 105.16,9.27 ; H4.1 99.57,6.99 ; H4.1 98.42,9.27 ; C158.2 v1(102.49,84.07) ; v1(52.45,63.88) 51.94,63.37 C32.2 ; 101.47,17.02 v1(99.44,17.02) 97.41,17.02 v1(96.46,17.97) 94.61,19.81 C131.2 ; 101.47,17.02 v1(103.63,17.02) ; 101.47,17.02 101.47,16.32 101.16,16 v1(99.44,16) 97.03,16 96.39,16.64 v1(95.12,16.64) 94.36,17.4 93.47,17.4 ; C91.2 62.36,31.11 v1(62.87,30.61) ; J16.14 115.82,36.96 ; R137.2 81.03,16.26 v1(81.15,16.38) ; C6.2 v1(50.55,35.05) ; R121.2 82.04,25.02 v1(82.17,25.15) ; J23.5 121.89,85.44 v1(121.22,84.77) ; v1(136.27,47.75) 136.02,48.01 R205.2 ; C42.2 v1(25.77,47.62) ; SW5.1 v1(88.3,86.96) ; C23.2 v1(38.23,47.88) C79.2 ; v1(65.02,21.84) 64.77,22.1 C117.2 ; v1(44.45,60.71) 44.46,60.7 C46.2 ; U12.2 v1(101.85,15.24) ; C90.2 v1(44.2,83.57) ; R57.2 72.77,39.75 v1(73.41,39.12) ; v1(78.99,22.86) 78.99,22.6 R127.2 ; U14.52 v1(102.65,51.18) ; TVS5.1 v1(60.2,4.57) ; v1(53.26,69.72) 53.33,69.65 C87.2 ; Y4.4 v1(38.9,38.95) ; v1(70.1,59.18) 69.6,59.18 v1(68.58,58.17) ; R140.2 v1(29.22,73.02) ; C17.2 45.72,55.89 v1(45.72,55.89) ; C25.2 v1(47.37,34.8) ; v1(25.27,54.86) 25.59,54.54 U2.1 ; R91.2 56.13,20.71 v1(56.13,20.95) C100.2 ; R152.2 v1(108.2,46.99) ; J15.SH3 v1(27.54,71.14) ; Y3.2 v1(118.49,71.25) ; J15.SH4 v1(20.46,69.73) ; C24.2 43.94,48.51 C44.2 v1(42.8,48.13) ; C133.2 93.98,14.35 94.36,14.73 v1(94.36,15.11) 95.76,15.11 96.39,14.48 v1(97.79,14.48) v1(100.2,14.48) 101.09,14.48 v1(101.85,13.72) ; U14.54 v1(104.25,47.87) ; v1(118.11,69.22) 118.62,69.22 118.87,69.47 119.13,69.47 121.54,71.88 v1(121.54,72.14) ; C78.2 44.7,46.35 v1(44.32,45.97) ; R244.2 v1(59.69,88) ; v1(79.5,10.03) 79.5,10.8 R125.2 ; C89.2 v1(51.56,82.8) ; C104.2 v1(55.38,18.17) ; C162.2 121.79,82.42 v1(121.4,82.42) U19.2 ; C161.2 v1(120.27,73.03) ; C137.2 v1(86.49,10.03) ; C55.2 v1(52.45,65.15) ; v1(40.26,52.58) 40.26,52.7 40.77,53.21 C140.2 ; C30.2 v1(25.52,57.03) ; R196.2 v1(119.89,66.93) ; v1(5.71,42.04) 5.36,42.39 J9.5 ; U14.6 v1(100.25,62.66) ; C66.2 v1(47.5,31.62) ; C170.2 v1(54.36,83.44) ; C169.2 v1(64.77,77.85) ; Q1.3 v1(19.19,2.41) ; U18.2 v1(128.54,84.44) ; C98.2 v1(59.95,24.26) ; R151.2 v1(117.61,46.22) ; C7.2 v1(50.55,34.04) ; C76.2 42.03,55.37 C77.2 42.67,55.5 v1(42.93,55.24) ; C121.1 v1(50.04,22.22) ; v1(62.99,22.99) 62.74,23.24 C116.2 ; R150.2 v1(120.02,46.22) ; C20.2 v1(42.29,37.72) ; C118.2 v1(65.79,21.84) ; C168.2 v1(54.36,84.58) ; v1(24.77,83.06) 24.77,83.05 J15.6 24.77,80.27 v1(24.77,80.26) ; R131.2 v1(81.27,18.79) ; v1(47.62,63.37) C31.2 48.5,62.38 C33.2 ; C149.2 v1(82.42,57.4) ; U9.2 43.81,71.5 v1(43.69,71.63) 43.44,71.88 C86.2 42.79,72.01 C85.2 ; C124.2 v1(50.03,26.55) ; C127.2 v1(89.15,10.03) ; C108.2 63.5,26.68 v1(63.5,26.16) 62.87,26.16 C110.1 ; R211.2 v1(134.37,78.61) ; C135.2 v1(108.58,12.57) ; SW5.2 v1(101.6,86.96) ; R133.2 v1(82.42,10.17) ; R246.2 v1(67.94,82.42) ; v1(71.63,50.04) 72.01,49.66 C75.2 ; C71.2 v1(46.61,31.62) ; C35.2 v1(42.93,59.94) 42.82,59.83 C18.2 ; C155.2 v1(118.24,84.96) ; C56.2 v1(38.99,35.94) ; R122.2 R120.2 84.96,25.02 v1(84.71,25.27) ; v1(82.55,61.21) R263.1 ; C154.2 v1(125.98,67.06) ; D11.3 v1(46.65,85.05) ; v1(52.45,20.32) 52.83,20.7 C95.2 ; C47.2 v1(38.86,29.46) ; U14.12 95.45,62.43 v1(95.63,62.61) ; R213.2 v1(133.1,75.18) ; v1(33.02,46.99) 32.64,46.61 C48.2 ; C43.2 v1(25.78,50.42) ; v1(59.4,10.29) TVS4.1 ; C120.1 v1(50.04,28.82) ; C153.2 v1(115.82,61.21) ; TVS2.1 v1(42.84,12.53) ; C180.2 v1(37.85,73.91) ; v1(60.07,7.41) TVS3.1 ; C167.2 v1(62.61,88.14) ; U13.4 v1(69.09,72.39) ; 53.98,22.1 v1(53.98,22.99) ; v1(37.85,54.22) C141.2 ; C163.2 v1(105.03,85.47) ; C159.2 v1(131.57,83.06) ; R203.2 v1(130.68,78.99) ; J15.SH2 v1(16,85.34) ; U14.46 v1(97.85,47.89) ; C119.2 67.94,26.54 v1(67.44,26.04) 67.44,25.65 R103.1 ; C26.2 v1(46.35,34.8) ; C174.2 v1(9.27,57.91) ; C126.2 v1(90.17,10.16)
  TOP w0.508: H2.1 137.41,87.88 ; H2.1 133.1,87.88 ; H2.1 132.28,85.72 ; H2.1 135.25,88.7 ; H2.1 138.23,85.72 ; H2.1 135.25,82.75 ; H2.1 133.1,83.57 ; H2.1 137.41,83.57 ; SW1.3 23.04,19.81 ; SW1.3 22.87,20.39 ; SW1.3 22.87,19.23 ; SW1.3 21.71,19.23 ; SW1.3 21.54,19.81 ; SW1.3 21.71,20.39 ; SW1.3 22.29,19.06 ; SW1.3 22.29,20.56 ; 117.3,38.48 J16.12 ; J16.12 117.56,39.29 ; J16.12 117.56,37.68 ; J16.12 118.36,39.55 ; J16.12 119.17,37.68 ; J16.12 119.43,38.48 ; J16.12 119.17,39.29 ; J16.12 118.36,37.41 ; J11.1 54.57,1 ; J11.1 53.85,3.47 ; J11.1 54.57,2.24 ; J11.1 53.12,1 ; J11.1 53.12,3.47 ; J11.1 54.57,3.47 ; J11.1 53.12,2.24 ; J11.1 53.85,1 ; 134.37,26.35 TP4.1 ; TP4.1 133.03,27.69 ; TP4.1 134.37,29.02 ; TP4.1 135.7,27.69 ; TP4.1 135.36,28.68 ; TP4.1 135.36,26.69 ; TP4.1 133.37,28.68 ; TP4.1 133.37,26.69 ; 119.84,38.48 J16.10 ; J16.10 121.97,38.48 ; J16.10 121.71,39.29 ; J16.10 120.1,39.29 ; J16.10 120.9,39.55 ; J16.10 121.71,37.68 ; J16.10 120.9,37.41 ; J16.10 120.1,37.68 ; H3.1 6.09,18.03 ; H3.1 6.09,13.72 ; H3.1 1.78,13.72 ; H3.1 1.78,18.03 ; H3.1 3.94,12.9 ; H3.1 6.91,15.88 ; H3.1 3.94,18.85 ; H3.1 0.96,15.88 ; J1.8 31.5,18.92 ; J1.8 31.25,18.15 ; J1.8 29.71,18.15 ; J1.8 30.48,19.94 ; J1.8 29.71,19.69 ; J1.8 31.25,19.69 ; J1.8 30.48,17.91 ; J1.8 29.46,18.92 ; 8.83,85.34 TP5.1 ; TP5.1 11.15,84.35 ; TP5.1 10.16,86.68 ; TP5.1 9.17,86.34 ; TP5.1 9.17,84.35 ; TP5.1 10.16,84.01 ; TP5.1 11.15,86.34 ; TP5.1 11.49,85.34 ; J2.2 8.03,6.73 ; J2.2 8.03,4.67 ; J2.2 6.13,4.67 ; J2.2 7.08,8.79 ; J2.2 7.08,4.67 ; J2.2 8.03,8.79 ; J2.2 6.13,6.73 ; J2.2 6.13,8.79 ; J2.3 12.64,2.88 ; J2.3 10.58,0.98 ; J2.3 12.64,0.98 ; J2.3 10.58,2.88 ; J2.3 8.52,1.93 ; J2.3 12.64,1.93 ; J2.3 8.52,2.88 ; J2.3 8.52,0.98 ; TP3.1 4.8,20.72 ; TP3.1 2.82,20.72 ; TP3.1 2.82,22.71 ; TP3.1 3.81,20.38 ; TP3.1 2.48,21.72 ; TP3.1 4.8,22.71 ; TP3.1 3.81,23.05 ; TP3.1 5.14,21.72 ; J7.1 29.01,46.81 ; J7.1 27.13,46.81 ; J7.1 28.07,48.69 ; J7.1 27.13,48.69 ; J7.1 27.13,47.75 ; J7.1 29.01,47.75 ; J7.1 29.01,48.69 ; J7.1 28.07,46.81 ; 29.71,20.69 J1.10 ; J1.10 30.48,22.48 ; J1.10 31.5,21.46 ; J1.10 31.25,22.23 ; J1.10 29.71,22.23 ; J1.10 31.25,20.69 ; J1.10 29.46,21.46 ; J1.10 30.48,20.45 ; H1.1 6.09,83.57 ; H1.1 1.78,87.88 ; H1.1 6.09,87.88 ; H1.1 1.78,83.57 ; H1.1 3.94,82.75 ; H1.1 0.96,85.72 ; H1.1 3.94,88.7 ; H1.1 6.91,85.72 ; J1.7 33.79,19.69 ; J1.7 33.02,17.91 ; J1.7 32.25,18.15 ; J1.7 34.04,18.92 ; J1.7 32,18.92 ; J1.7 32.25,19.69 ; J1.7 33.02,19.94 ; J1.7 33.79,18.15 ; J20.6 103.05,76.25 ; J20.6 101.29,75.49 ; J20.6 101.05,76.25 ; J20.6 101.29,77.01 ; J20.6 102.81,77.01 ; J20.6 102.05,75.24 ; J20.6 102.81,75.49 ; J20.6 102.05,77.25 ; 109.68,38.48 J16.18 ; J16.18 109.94,39.29 ; J16.18 111.55,37.68 ; J16.18 110.74,39.55 ; J16.18 111.81,38.48 ; J16.18 111.55,39.29 ; J16.18 110.74,37.41 ; J16.18 109.94,37.68 ; 135.53,81.13 TP2.1 ; TP2.1 136.53,78.8 ; TP2.1 137.86,80.14 ; TP2.1 135.19,80.14 ; TP2.1 137.52,79.14 ; TP2.1 137.52,81.13 ; TP2.1 135.53,79.14 ; TP2.1 136.53,81.47 ; 32.25,20.69 J1.9 ; J1.9 32.25,22.23 ; J1.9 34.04,21.46 ; J1.9 32,21.46 ; J1.9 33.79,22.23 ; J1.9 33.02,22.48 ; J1.9 33.79,20.69 ; J1.9 33.02,20.45 ; 98.75,75.49 J20.7 ; J20.7 100.51,76.25 ; J20.7 99.51,77.25 ; J20.7 98.75,77.01 ; J20.7 98.51,76.25 ; J20.7 100.27,77.01 ; J20.7 100.27,75.49 ; J20.7 99.51,75.24 ; 46.8,87.25 J10.2 ; J10.2 48.46,86.53 ; J10.2 48.68,87.25 ; J10.2 47.74,88.19 ; J10.2 48.46,87.96 ; J10.2 47.02,87.96 ; J10.2 47.02,86.53 ; J10.2 47.74,86.31 ; J16.20 108.2,39.55 ; J16.20 109.01,39.29 ; J16.20 107.14,38.48 ; J16.20 109.27,38.48 ; J16.20 109.01,37.68 ; J16.20 108.2,37.41 ; J16.20 107.4,37.68 ; J16.20 107.4,39.29
  BOTTOM w0.127: 86.53,63.25 86.53,62.23 ; 85.66,63.12 85.66,62.23
  BOTTOM w0.381: C178.2 57.78,58.67 v1(57.78,58.04) 57.91,57.91 C69.2 ; v1(83.19,51.05) 82.42,50.29 R261.1 ; v1(51.69,60.71) 51.44,60.45 C10.2 ; v1(67.18,58.04) C70.2 ; R257.1 v1(89.79,51.05) ; C138.2 v1(24.26,79.12) ; C17.2 45.72,55.89 v1(45.72,55.89) ; J16.4 127.64,39.37 ; J16.4 129.41,39.37 ; J16.4 127.51,37.47 ; J16.4 129.41,37.59 ; v1(67.18,52.96) 67.05,52.83 C9.2 ; 107.82,83.31 108.46,83.95 107.31,83.95 ; C72.2 62.48,57.91 v1(62.36,58.04) 62.36,58.54 C177.2 ; C74.2 v1(67.18,40.01) 67.81,40.01 C176.2 ; R178.2 v1(94.36,51.05) ; v1(67.16,41.89) 67.01,42.04 C12.2 ; R255.1 v1(93.34,51.05) ; R256.1 v1(90.68,51.05) ; J19.7 117.16,27.1 ; J19.7 117.16,28.88 ; J19.7 115.38,28.88 ; J19.7 115.26,26.97 ; C15.2 55,39.5 v1(54.86,39.37) ; v1(56.26,23.5) 56.01,23.75 C97.2 ; C146.2 v1(103.38,56.26) ; C99.2 v1(51.82,24.64) ; v1(54.23,58.04) 54.36,57.91 C73.2 ; R260.1 v1(84.96,51.05) ; v1(59.06,67.57) C142.2 58.93,68.59 C143.2 ; 107.31,85.22 J29.3 107.82,84.58 ; C13.2 v1(62.49,39.37) ; C16.2 v1(55,42.16) ; C144.2 v1(102.62,54.1) ; C8.2 64.14,57.91 v1(64.01,58.04) ; R258.1 v1(87.12,51.05) ; 23.5,78.11 v1(24.38,78.11) ; C67.2 v1(64.14,39.37) ; C145.2 v1(101.73,56.26) ; C14.2 v1(61.72,41.27)
  BOTTOM w0.508: J16.8 124.25,39.29 ; J16.8 123.44,37.41 ; J16.8 123.44,39.55 ; J16.8 122.64,39.29 ; J16.8 122.64,37.68 ; J16.8 122.38,38.48 ; J16.8 124.25,37.68 ; J16.8 124.51,38.48 ; J1.9 33.79,22.23 ; J1.9 34.04,21.46 ; J1.9 32.25,20.69 ; J1.9 32,21.46 ; J1.9 33.02,20.45 ; J1.9 33.79,20.69 ; J1.9 32.25,22.23 ; J1.9 33.02,22.48 ; 102.05,75.24 J20.6 ; J20.6 101.05,76.25 ; J20.6 101.29,77.01 ; J20.6 103.05,76.25 ; J20.6 102.81,75.49 ; J20.6 101.29,75.49 ; J20.6 102.05,77.25 ; J20.6 102.81,77.01 ; J2.2 8.03,8.79 ; J2.2 8.03,4.67 ; J2.2 6.13,4.67 ; J2.2 6.13,6.73 ; J2.2 7.08,4.67 ; J2.2 6.13,8.79 ; J2.2 8.03,6.73 ; J2.2 7.08,8.79 ; 21.54,19.81 SW1.3 ; SW1.3 22.29,19.06 ; SW1.3 22.87,20.39 ; SW1.3 21.71,20.39 ; SW1.3 22.87,19.23 ; SW1.3 23.04,19.81 ; SW1.3 22.29,20.56 ; SW1.3 21.71,19.23 ; 120.9,37.41 J16.10 ; J16.10 121.71,37.68 ; J16.10 120.1,37.68 ; J16.10 119.84,38.48 ; J16.10 120.9,39.55 ; J16.10 121.71,39.29 ; J16.10 120.1,39.29 ; J16.10 121.97,38.48 ; J16.14 115.82,39.55 ; J16.14 116.63,39.29 ; J16.14 115.02,37.68 ; J16.14 114.76,38.48 ; J16.14 116.89,38.48 ; J16.14 115.82,37.41 ; J16.14 115.02,39.29 ; J16.14 116.63,37.68 ; J1.7 33.02,19.94 ; J1.7 32.25,19.69 ; J1.7 32,18.92 ; J1.7 33.02,17.91 ; J1.7 33.79,19.69 ; J1.7 33.79,18.15 ; J1.7 32.25,18.15 ; J1.7 34.04,18.92 ; 27.13,46.81 J7.1 ; J7.1 27.13,47.75 ; J7.1 29.01,46.81 ; J7.1 29.01,47.75 ; J7.1 29.01,48.69 ; J7.1 28.07,48.69 ; J7.1 27.13,48.69 ; J7.1 28.07,46.81 ; H1.1 6.09,87.88 ; H1.1 6.09,83.57 ; H1.1 6.91,85.72 ; H1.1 1.78,87.88 ; H1.1 1.78,83.57 ; H1.1 0.96,85.72 ; H1.1 3.94,88.7 ; H1.1 3.94,82.75 ; 124.92,38.48 J16.6 ; J16.6 126.79,37.68 ; J16.6 125.18,37.68 ; J16.6 125.98,39.55 ; J16.6 126.79,39.29 ; J16.6 125.98,37.41 ; J16.6 127.05,38.48 ; J16.6 125.18,39.29 ; 133.03,27.69 TP4.1 ; TP4.1 135.7,27.69 ; TP4.1 134.37,26.35 ; TP4.1 135.36,28.68 ; TP4.1 133.37,28.68 ; TP4.1 135.36,26.69 ; TP4.1 134.37,29.02 ; TP4.1 133.37,26.69 ; J16.16 113.28,39.55 ; J16.16 113.28,37.41 ; J16.16 112.48,39.29 ; J16.16 112.22,38.48 ; J16.16 114.09,37.68 ; J16.16 114.35,38.48 ; J16.16 112.48,37.68 ; J16.16 114.09,39.29 ; J1.8 31.25,18.15 ; J1.8 29.71,19.69 ; J1.8 31.5,18.92 ; J1.8 31.25,19.69 ; J1.8 30.48,19.94 ; J1.8 29.46,18.92 ; J1.8 29.71,18.15 ; J1.8 30.48,17.91 ; 2.82,20.72 TP3.1 ; TP3.1 2.48,21.72 ; TP3.1 3.81,23.05 ; TP3.1 5.14,21.72 ; TP3.1 2.82,22.71 ; TP3.1 4.8,20.72 ; TP3.1 4.8,22.71 ; TP3.1 3.81,20.38 ; 109.94,39.29 J16.18 ; J16.18 110.74,39.55 ; J16.18 111.55,39.29 ; J16.18 111.55,37.68 ; J16.18 109.94,37.68 ; J16.18 109.68,38.48 ; J16.18 111.81,38.48 ; J16.18 110.74,37.41 ; J20.7 100.27,77.01 ; J20.7 98.75,77.01 ; J20.7 99.51,75.24 ; J20.7 100.51,76.25 ; J20.7 100.27,75.49 ; J20.7 98.75,75.49 ; J20.7 99.51,77.25 ; J20.7 98.51,76.25 ; J16.12 119.17,39.29 ; J16.12 119.43,38.48 ; J16.12 119.17,37.68 ; J16.12 118.36,37.41 ; J16.12 117.56,37.68 ; J16.12 117.3,38.48 ; J16.12 117.56,39.29 ; J16.12 118.36,39.55 ; J2.3 12.64,1.93 ; J2.3 10.58,0.98 ; J2.3 10.58,2.88 ; J2.3 12.64,2.88 ; J2.3 8.52,2.88 ; J2.3 12.64,0.98 ; J2.3 8.52,1.93 ; J2.3 8.52,0.98 ; SW1.6 22.29,18.06 ; SW1.6 21.71,17.89 ; SW1.6 22.87,16.73 ; SW1.6 21.71,16.73 ; SW1.6 21.54,17.31 ; SW1.6 22.87,17.89 ; SW1.6 23.04,17.31 ; SW1.6 22.29,16.56 ; 99.7,11.42 H4.1 ; H4.1 98.88,9.27 ; H4.1 99.7,7.12 ; H4.1 101.85,6.3 ; H4.1 101.85,12.24 ; H4.1 104.01,11.42 ; H4.1 104.83,9.27 ; H4.1 104.01,7.12 ; 135.25,82.75 H2.1 ; H2.1 138.23,85.72 ; H2.1 132.28,85.72 ; H2.1 135.25,88.7 ; H2.1 137.41,87.88 ; H2.1 133.1,83.57 ; H2.1 133.1,87.88 ; H2.1 137.41,83.57 ; 53.12,1 J11.1 ; J11.1 54.57,2.24 ; J11.1 54.57,3.47 ; J11.1 53.12,2.24 ; J11.1 54.57,1 ; J11.1 53.85,3.47 ; J11.1 53.85,1 ; J11.1 53.12,3.47 ; 47.02,86.53 J10.2 ; J10.2 48.46,87.96 ; J10.2 47.74,88.19 ; J10.2 47.02,87.96 ; J10.2 48.46,86.53 ; J10.2 47.74,86.31 ; J10.2 46.8,87.25 ; J10.2 48.68,87.25 ; 9.17,84.35 TP5.1 ; TP5.1 9.17,86.34 ; TP5.1 10.16,84.01 ; TP5.1 11.15,86.34 ; TP5.1 11.15,84.35 ; TP5.1 11.49,85.34 ; TP5.1 8.83,85.34 ; TP5.1 10.16,86.68 ; 3.94,12.9 H3.1 ; H3.1 6.09,18.03 ; H3.1 3.94,18.85 ; H3.1 1.78,13.72 ; H3.1 1.78,18.03 ; H3.1 6.91,15.88 ; H3.1 0.96,15.88 ; H3.1 6.09,13.72 ; J16.20 109.27,38.48 ; J16.20 108.2,39.55 ; J16.20 107.4,37.68 ; J16.20 108.2,37.41 ; J16.20 107.4,39.29 ; J16.20 109.01,37.68 ; J16.20 109.01,39.29 ; J16.20 107.14,38.48 ; J1.10 31.25,20.69 ; J1.10 29.46,21.46 ; J1.10 29.71,20.69 ; J1.10 31.5,21.46 ; J1.10 30.48,20.45 ; J1.10 30.48,22.48 ; J1.10 31.25,22.23 ; J1.10 29.71,22.23 ; TP2.1 137.52,81.13 ; TP2.1 135.53,79.14 ; TP2.1 135.53,81.13 ; TP2.1 136.53,78.8 ; TP2.1 137.52,79.14 ; TP2.1 135.19,80.14 ; TP2.1 137.86,80.14 ; TP2.1 136.53,81.47
  vias: v1(0.76,83.82) v1(0.76,80.26) v1(0.76,76.83) v1(0.76,73.66) v1(0.76,70.1) v1(0.76,66.8) v1(0.76,63.5) v1(0.76,59.94) v1(0.76,56.52) v1(0.76,53.34) v1(0.76,37.08) v1(0.76,33.53) v1(0.76,30.23) v1(0.76,26.92) v1(0.76,23.37) v1(0.76,19.94) v1(0.89,8.26) v1(0.89,4.7) v1(0.89,1.27) v1(1.14,89.03) v1(1.65,53.72) v1(1.65,52.83) v1(2.54,53.72) v1(2.54,52.83) v1(3.56,53.72) v1(3.56,52.83) v1(4.7,89.03) v1(4.83,51.69) v1(4.83,50.16) v1(4.83,49.15) v1(4.83,48.01) v1(4.83,8.26) v1(4.83,4.7) v1(4.83,1.27) v1(5.46,51.05) v1(5.46,48.39) v1(5.46,44.96) v1(5.46,40.39) v1(6.6,44.83) v1(6.73,24) v1(6.73,20.19) v1(8,89.03) v1(8.38,49.02) v1(8.89,75.31) v1(8.89,48.39) v1(8.89,40.39) v1(9.27,44.91) v1(9.27,36.45) v1(9.27,32) v1(9.27,27.81) v1(9.4,49.02) v1(10.85,41.53) v1(10.92,48.77) v1(11.18,80.77) v1(11.18,77.22) v1(11.18,73.79) v1(11.18,70.1) v1(11.18,66.55) v1(11.18,63.12) v1(11.18,59.69) v1(11.18,23.62) v1(11.56,89.03) v1(11.56,56.52) v1(12.19,55.24) v1(12.83,12.06) v1(13.08,50.55) v1(13.08,49.4) v1(13.97,65.15) v1(13.97,62.74) v1(14.61,69.98) v1(14.61,67.69) v1(14.61,54.99) v1(14.61,14.35) v1(14.73,89.03) v1(15.37,66.17) v1(15.37,31.11) v1(16,66.8) v1(16,32.77) v1(16,11.94) v1(16.38,78.61) v1(16.38,75.06) v1(16.38,71.63) v1(16.76,38.73) v1(16.76,29.72) v1(17.14,31.62) v1(17.53,68.07) v1(17.53,14.35) v1(17.65,69.98) v1(18.16,89.03) v1(18.16,0.76) v1(18.41,39.5) v1(18.8,63.88) v1(19.05,10.13) v1(19.18,31.5) v1(19.3,62.36) v1(19.43,40.51) v1(19.56,12.19) v1(19.81,75.06) v1(19.81,68.07) v1(19.81,67.06) v1(19.81,14.35) v1(19.94,36.07) v1(20.32,84.58) v1(20.7,55.12) v1(20.95,79.76) v1(21.08,64.14) v1(21.08,41.53) v1(21.34,68.07) v1(21.34,0.76) v1(21.72,89.03) v1(21.84,14.35) v1(21.97,58.8) v1(22.35,60.45) v1(22.35,41.53) v1(22.73,38.86) v1(22.99,68.07) v1(22.99,31.5) v1(23.24,64.14) v1(23.5,11.94) v1(23.75,13.59) v1(24,61.72) v1(24.13,69.72) v1(24.64,84.58) v1(24.89,0.76) v1(25.02,89.03) v1(25.15,8.64) v1(25.4,55.88) v1(25.4,14.35) v1(25.78,66.29) v1(26.42,60.96) v1(26.54,80.01) v1(26.54,13.08) v1(27.69,27.43) v1(27.69,0.76) v1(27.81,56.39) v1(28.32,89.03) v1(28.32,58.8) v1(29.08,68.2) v1(29.08,61.47) v1(29.08,41.27) v1(29.21,71.63) v1(29.59,25.02) v1(29.59,23.75) v1(29.97,52.96) v1(30.1,67.31) v1(30.1,61.21) v1(30.1,27.43) v1(30.86,52.96) v1(30.86,0.76) v1(31.1,80.08) v1(31.24,23.75) v1(31.35,82.75) v1(31.75,78.11) v1(31.88,89.03) v1(32,42.29) v1(33.66,45.97) v1(33.66,3.05) v1(33.66,0.76) v1(33.87,80.23) v1(34.91,84.65) v1(35.05,89.03) v1(35.05,42.16) v1(35.18,68.33) v1(35.18,67.31) v1(35.43,18.41) v1(35.69,73.66) v1(35.69,45.97) v1(35.69,13.97) v1(36.07,49.02) v1(36.07,16.89) v1(36.32,68.45) v1(36.58,71.5) v1(36.7,73.66) v1(36.83,3.05) v1(36.83,0.76) v1(37.08,76.2) v1(37.08,36.32) v1(37.34,32.51) v1(37.34,15.62) v1(37.42,82.14) v1(37.59,68.45) v1(38.48,89.03) v1(38.48,68.45) v1(38.61,76.2) v1(38.61,71.5) v1(38.86,8.26) v1(38.86,7.24) v1(38.99,32.51) v1(38.99,26.54) v1(39.12,77.72) v1(39.24,84.71) v1(39.24,79.76) v1(39.24,67.31) v1(39.24,66.04) v1(39.5,74.55) v1(39.62,73.15) v1(39.62,37.72) v1(39.62,13.34) v1(39.88,8.26) v1(39.88,7.24) v1(39.88,6.1) v1(39.88,4.95) v1(40.13,66.04) v1(40.26,24.89) v1(40.39,73.91) v1(40.39,3.17) v1(40.39,0.76) v1(40.64,72.26) v1(40.64,71.25) v1(41.15,82.17) v1(41.15,76.71) v1(41.15,66.04) v1(41.4,86.49) v1(41.91,38.48) v1(42.04,89.03) v1(42.04,60.71) v1(42.04,23.11) v1(42.8,60.71) v1(42.9,45.85) v1(42.93,32.77) v1(43.05,34.42) v1(43.05,29.34) v1(43.05,27.69) v1(43.18,0.76) v1(43.43,3.3) v1(43.69,69.09) v1(43.69,60.71) v1(43.69,38.48) v1(43.69,20.83) v1(43.69,19.81) v1(43.94,25.65) v1(43.94,23.24) v1(44.07,80.14) v1(44.07,78.11) v1(44.07,75.44) v1(44.83,33.02) v1(45.09,34.54) v1(45.21,8.89) v1(45.72,65.02) v1(45.72,27.81) v1(46.23,77.72) v1(46.23,76.2) v1(46.35,0.76) v1(46.48,24.38) v1(46.74,69.85) v1(46.86,63.88) v1(47.24,37.59) v1(47.75,79.63) v1(48.33,55.88) v1(48.39,69.85) v1(48.39,68.58) v1(48.51,48.13) v1(48.51,42.16) v1(48.51,39.5) v1(48.64,72.26) v1(48.64,52.7) v1(48.64,51.69) v1(49.02,30.61) v1(49.15,77.72) v1(49.15,76.2) v1(49.66,19.05) v1(49.78,24.26) v1(49.91,0.89) v1(50.16,31.75) v1(50.32,52.58) v1(50.32,50.8) v1(50.42,48.77) v1(50.42,46.74) v1(50.42,44.58) v1(50.42,42.16) v1(50.42,40.51) v1(51.18,35.56) v1(51.56,79.38) v1(51.56,75.44) v1(51.56,29.34) v1(51.82,71.5) v1(51.82,69.98) v1(51.94,68.33) v1(51.94,19.05) v1(52.32,22.1) v1(52.58,36.58) v1(52.58,31.55) v1(52.7,60.71) v1(52.74,52.7) v1(52.74,49.28) v1(52.74,45.72) v1(52.74,41.91) v1(52.83,27.81) v1(52.96,88.14) v1(54,52.45) v1(54,49.02) v1(54,45.47) v1(54,42.04) v1(53.98,39.37) v1(53.98,34.16) v1(53.98,18.54) v1(54.1,30.23) v1(55.12,28.19) v1(55.12,25.4) v1(55.24,58.04) v1(55.24,34.42) v1(55.37,79.76) v1(55.37,76.83) v1(55.37,55.37) v1(55.37,52.2) v1(55.37,48.77) v1(55.37,45.21) v1(55.75,0.89) v1(56.13,88.14) v1(56.52,12.57) v1(56.64,78.36) v1(56.64,68.05) v1(56.77,55.24) v1(57.02,65.79) v1(57.02,10.16) v1(57.02,8.26) v1(57.53,39.37) v1(57.66,18.16) v1(57.91,77.22) v1(57.91,28.19) v1(57.91,25.4) v1(58.42,52.2) v1(58.42,48.77) v1(58.42,45.21) v1(58.42,42.67) v1(58.67,18.16) v1(58.93,0.89) v1(59.18,55.24) v1(59.56,57.91) v1(60.2,39.37) v1(60.2,33.53) v1(61.09,52.2) v1(61.09,48.77) v1(61.09,45.21) v1(61.09,42.67) v1(61.09,8.26) v1(61.34,23.5) v1(61.47,33.27) v1(61.72,26.16) v1(61.85,55.24) v1(61.85,19.43) v1(62.48,70.36) v1(62.48,0.89) v1(63.75,17.78) v1(64.14,53.34) v1(64.14,51.05) v1(64.14,47.75) v1(64.14,44.83) v1(64.14,41.53) v1(64.39,29.08) v1(64.52,87.76) v1(65.28,16.31) v1(65.41,19.43) v1(65.53,80.39) v1(65.66,0.89) v1(66.42,73.91) v1(66.67,20.57) v1(66.8,89.03) v1(66.8,39.24) v1(66.93,15.49) v1(66.93,13.84) v1(67.18,2.54) v1(67.31,54.61) v1(67.31,50.67) v1(67.31,47.5) v1(67.31,44.07) v1(67.44,59.31) v1(67.56,38.1) v1(67.94,83.82) v1(67.94,80.26) v1(67.94,21.21) v1(68.07,87.76) v1(68.45,73.91) v1(68.45,38.86) v1(68.83,0.89) v1(69.22,11.81) v1(69.34,19.94) v1(69.47,14.73) v1(69.6,77.72) v1(69.6,37.47) v1(69.98,84.96) v1(69.98,41.4) v1(70.1,89.03) v1(70.36,2.54) v1(70.48,74.3) v1(70.61,80.77) v1(70.61,72.39) v1(71.37,87.76) v1(71.5,20.83) v1(71.88,12.57) v1(71.88,9.4) v1(72.14,77.72) v1(72.39,0.89) v1(73.28,59.69) v1(73.28,37.59) v1(73.53,84.96) v1(73.66,89.03) v1(73.79,9.4) v1(73.91,2.54) v1(74.04,74.3) v1(74.17,80.77) v1(74.17,72.39) v1(74.93,87.76) v1(74.93,37.59) v1(75.44,57.4) v1(75.44,56.26) v1(75.69,77.72) v1(75.69,51.18) v1(75.82,0.89) v1(75.9,16.51) v1(76.45,52.07) v1(76.83,89.03) v1(76.83,84.96) v1(77.09,77.34) v1(77.09,75.95) v1(77.09,57.4) v1(77.09,56.26) v1(77.09,2.54) v1(77.22,51.18) v1(77.34,11.94) v1(77.47,80.77) v1(77.47,49.78) v1(77.6,55.24) v1(77.88,34.8) v1(78.11,87.76) v1(78.36,53.47) v1(78.61,18.41) v1(78.87,57.4) v1(78.87,56.26) v1(78.89,33.78) v1(78.99,0.89) v1(79.25,35.69) v1(79.5,52.32) v1(79.63,13.46) v1(79.76,50.93) v1(79.76,29.84) v1(80.14,55.24) v1(80.26,89.03) v1(80.26,53.21) v1(80.26,2.54) v1(80.39,84.96) v1(80.52,57.4) v1(80.52,56.26) v1(80.64,77.34) v1(80.77,32.64) v1(80.9,12.45) v1(81.03,80.77) v1(81.41,60.33) v1(81.53,87.76) v1(81.53,49.91) v1(81.66,34.42) v1(81.79,29.97) v1(82.42,55.24) v1(82.42,53.59) v1(82.55,59.18) v1(82.55,0.89) v1(82.68,56.26) v1(82.93,15.11) v1(83.19,32.89) v1(83.31,25.15) v1(83.57,84.96) v1(83.82,89.03) v1(83.82,2.54) v1(83.95,74.55) v1(84.2,80.77) v1(84.2,57.4) v1(84.45,22.86) v1(84.58,16.89) v1(84.96,77.34) v1(84.96,56.26) v1(84.96,36.83) v1(85.09,87.76) v1(85.6,0.89) v1(85.72,57.4) v1(85.85,26.04) v1(85.85,18.16) v1(86.11,74.3) v1(86.11,55.37) v1(86.11,53.34) v1(86.74,34.42) v1(86.87,89.03) v1(87,84.96) v1(87.12,18.8) v1(87.12,16.89) v1(87.25,2.54) v1(87.38,12.73) v1(87.63,80.77) v1(87.63,79.25) v1(87.76,26.04) v1(88.01,59.31) v1(88.14,22.61) v1(88.27,73.91) v1(88.27,57.28) v1(88.27,12.73) v1(88.52,77.34) v1(88.52,36.83) v1(88.77,0.89) v1(89.03,29.72) v1(89.03,22.99) v1(89.53,17.5) v1(89.66,57.28) v1(90.42,89.03) v1(90.42,2.54) v1(90.55,84.96) v1(90.93,31.75) v1(90.93,30.48) v1(91.06,59.44) v1(91.19,80.77) v1(91.19,79.25) v1(91.44,56.01) v1(91.44,54.61) v1(91.44,53.09) v1(91.95,36.83) v1(92.33,0.89) v1(92.46,88.77) v1(92.71,74.17) v1(92.71,59.44) v1(92.71,33.02) v1(93.47,56.01) v1(93.47,54.61) v1(93.47,53.09) v1(93.47,2.29) v1(93.85,36.83) v1(94.11,30.48) v1(94.23,22.48) v1(94.49,11.68) v1(94.49,9.4) v1(95.38,66.5) v1(95.5,0.89) v1(95.63,37.59) v1(95.76,59.44) v1(95.89,13.72) v1(96.01,88.77) v1(97.03,33.15) v1(97.28,2.29) v1(97.39,70.55) v1(97.41,55.63) v1(97.41,54.36) v1(97.41,53.09) v1(97.54,30.48) v1(97.66,26.29) v1(97.66,11.68) v1(97.66,9.4) v1(97.66,6.73) v1(97.92,39.88) v1(98.17,72.87) v1(98.3,22.48) v1(98.68,59.44) v1(98.68,0.89) v1(99.31,88.77) v1(99.31,36.7) v1(99.31,33.15) v1(99.57,74.27) v1(99.69,30.99) v1(99.91,68.04) v1(99.95,13.72) v1(100.46,42.42) v1(100.46,2.29) v1(100.69,70.36) v1(101.35,29.84) v1(101.6,24.77) v1(101.98,33.15) v1(102.08,71.76) v1(102.23,0.89) v1(102.33,65.62) v1(102.49,40.39) v1(102.49,36.7) v1(102.62,55.24) v1(102.62,44.58) v1(102.74,25.78) v1(102.87,88.77) v1(103.02,68.02) v1(103.25,30.99) v1(103.63,2.29) v1(103.76,24.26) v1(104.42,69.42) v1(105.03,46.99) v1(105.03,29.84) v1(105.03,25.78) v1(105.41,12.19) v1(105.54,65.51) v1(105.66,84.33) v1(105.66,81.79) v1(105.66,0.89) v1(105.79,23.88) v1(106.05,88.77) v1(106.68,30.99) v1(106.81,87.25) v1(106.81,51.18) v1(106.81,7.87) v1(106.93,66.91) v1(106.93,62.87) v1(106.93,59.69) v1(107.06,48.51) v1(107.06,13.59) v1(107.19,10.67) v1(107.19,2.29) v1(107.7,25.78) v1(107.7,16) v1(107.82,23.37) v1(108.46,20.57) v1(108.58,29.84) v1(108.84,79.38) v1(108.84,9.27) v1(108.84,0.89) v1(109.22,50.42) v1(109.47,88.77) v1(109.6,22.73) v1(110.11,48.9) v1(110.36,25.78) v1(110.36,7.87) v1(110.49,30.86) v1(110.62,10.16) v1(110.62,2.29) v1(110.87,16) v1(111.25,67.06) v1(111.25,62.74) v1(111.25,14.35) v1(111.38,85.47) v1(111.38,83.69) v1(111.38,81.15) v1(111.38,22.61) v1(111.38,13.08) v1(111.38,11.81) v1(111.51,87.38) v1(112.01,29.84) v1(112.27,79.38) v1(112.39,0.89) v1(112.78,25.65) v1(112.9,84.96) v1(112.9,50.42) v1(112.9,46.48) v1(112.9,20.57) v1(113.03,88.77) v1(113.67,24.89) v1(113.92,30.86) v1(114.17,2.29) v1(114.43,89.15) v1(114.43,88.39) v1(114.43,87.5) v1(114.43,78.11) v1(114.81,83.19) v1(114.81,74.17) v1(115.32,67.18) v1(115.44,89.15) v1(115.44,88.39) v1(115.57,45.59) v1(115.82,81.03) v1(115.82,25.4) v1(115.82,22.86) v1(115.95,0.76) v1(116.59,68.71) v1(116.71,76.58) v1(117.35,48.64) v1(117.6,80.14) v1(117.6,2.29) v1(117.73,16.38) v1(117.73,11.56) v1(117.86,75.06) v1(117.86,62.23) v1(117.98,63.88) v1(118.24,50.42) v1(118.49,13.72) v1(118.49,9.53) v1(118.75,61.19) v1(118.87,19.81) v1(119,79.76) v1(119.51,0.76) v1(120.52,69.22) v1(121.16,49.53) v1(121.16,2.67) v1(121.54,77.47) v1(121.54,74.68) v1(121.54,64.39) v1(122.17,67.82) v1(122.17,54.61) v1(122.43,61.21) v1(122.43,59.05) v1(122.81,84.2) v1(122.94,76.07) v1(122.94,0.76) v1(123.7,65.79) v1(123.7,63.88) v1(124.21,84.2) v1(124.21,71.37) v1(124.33,74.68) v1(124.33,5.71) v1(124.46,22.99) v1(124.46,19.43) v1(124.46,16.26) v1(124.46,12.83) v1(124.46,9.4) v1(124.71,64.77) v1(125.27,73.28) v1(125.73,58.93) v1(125.73,55.88) v1(125.86,52.58) v1(125.98,44.96) v1(126.11,0.76) v1(127,69.09) v1(127.64,50.16) v1(127.76,24.77) v1(127.76,23.62) v1(127.76,22.61) v1(127.89,86.23) v1(128.4,60.2) v1(128.78,68.07) v1(128.91,53.34) v1(128.91,24.77) v1(128.91,22.61) v1(128.91,18.92) v1(128.91,15.37) v1(128.91,12.19) v1(128.91,8.76) v1(128.91,5.21) v1(129.16,88.77) v1(129.16,85.22) v1(129.41,63.37) v1(129.67,58.17) v1(129.67,48.13) v1(129.67,0.76) v1(130.05,27.81) v1(130.81,70.99) v1(130.94,54.23) v1(131.57,49.53) v1(131.7,88.77) v1(131.7,85.22) v1(131.7,58.17) v1(132.33,47.88) v1(132.33,45.47) v1(132.46,78.74) v1(132.46,69.85) v1(133.22,31.11) v1(133.6,63.37) v1(133.6,54.23) v1(133.86,47.88) v1(133.99,49.53) v1(134.24,58.17) v1(135.38,31.11) v1(135.51,74.04) v1(135.51,73.03) v1(135.51,72.01) v1(136.4,74.04) v1(136.4,73.03) v1(136.4,72.01) v1(137.67,58.42) v1(138.18,54.36) v1(138.94,50.04) v1(138.94,46.48) v1(138.94,43.31) v1(138.94,39.88) v1(138.94,36.32) v1(138.94,31.88) v1(138.94,28.32) v1(138.94,25.15) v1(138.94,21.72) v1(138.94,18.16) v1(138.94,14.86) v1(138.94,11.3) v1(138.94,8.13) v1(138.94,4.7) v1(138.94,1.14) v1(139.06,88.39) v1(139.06,84.84) v1(139.06,81.53) v1(139.06,77.98) v1(139.06,74.8) v1(139.06,71.37) v1(139.06,67.82)
